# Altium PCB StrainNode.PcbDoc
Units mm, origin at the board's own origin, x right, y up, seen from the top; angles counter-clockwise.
Board outline 65 x 65 mm, 4 copper layers (Top Layer 1, GND, 3V3, Bottom Layer 1), stack 0.408 mm thick; 79 components, 56 nets, 295 pads, 250 vias.
Unrouted connection lines stored in the file: 29.
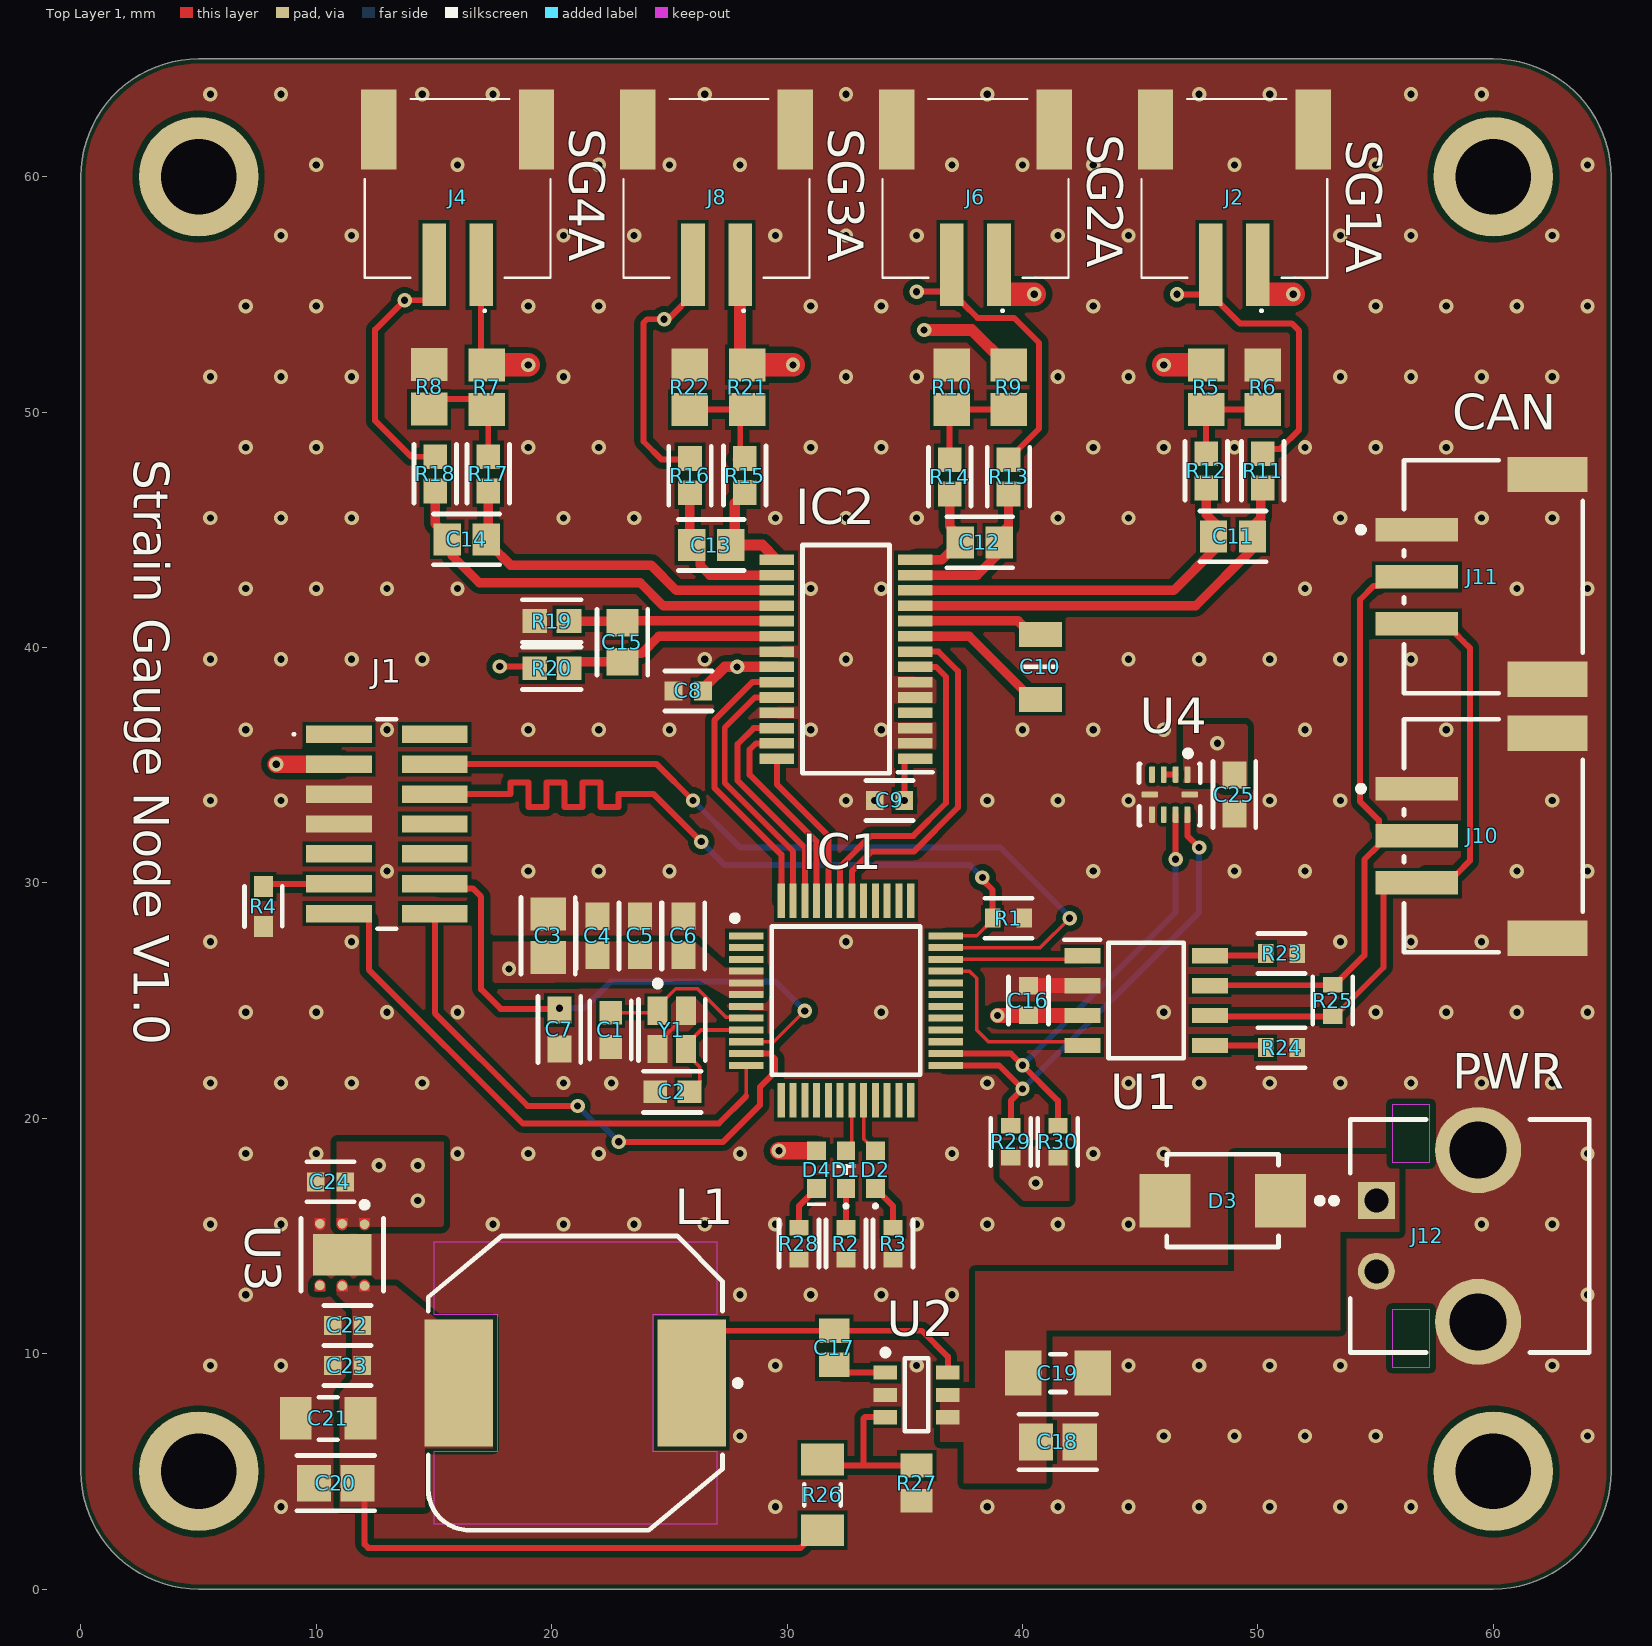
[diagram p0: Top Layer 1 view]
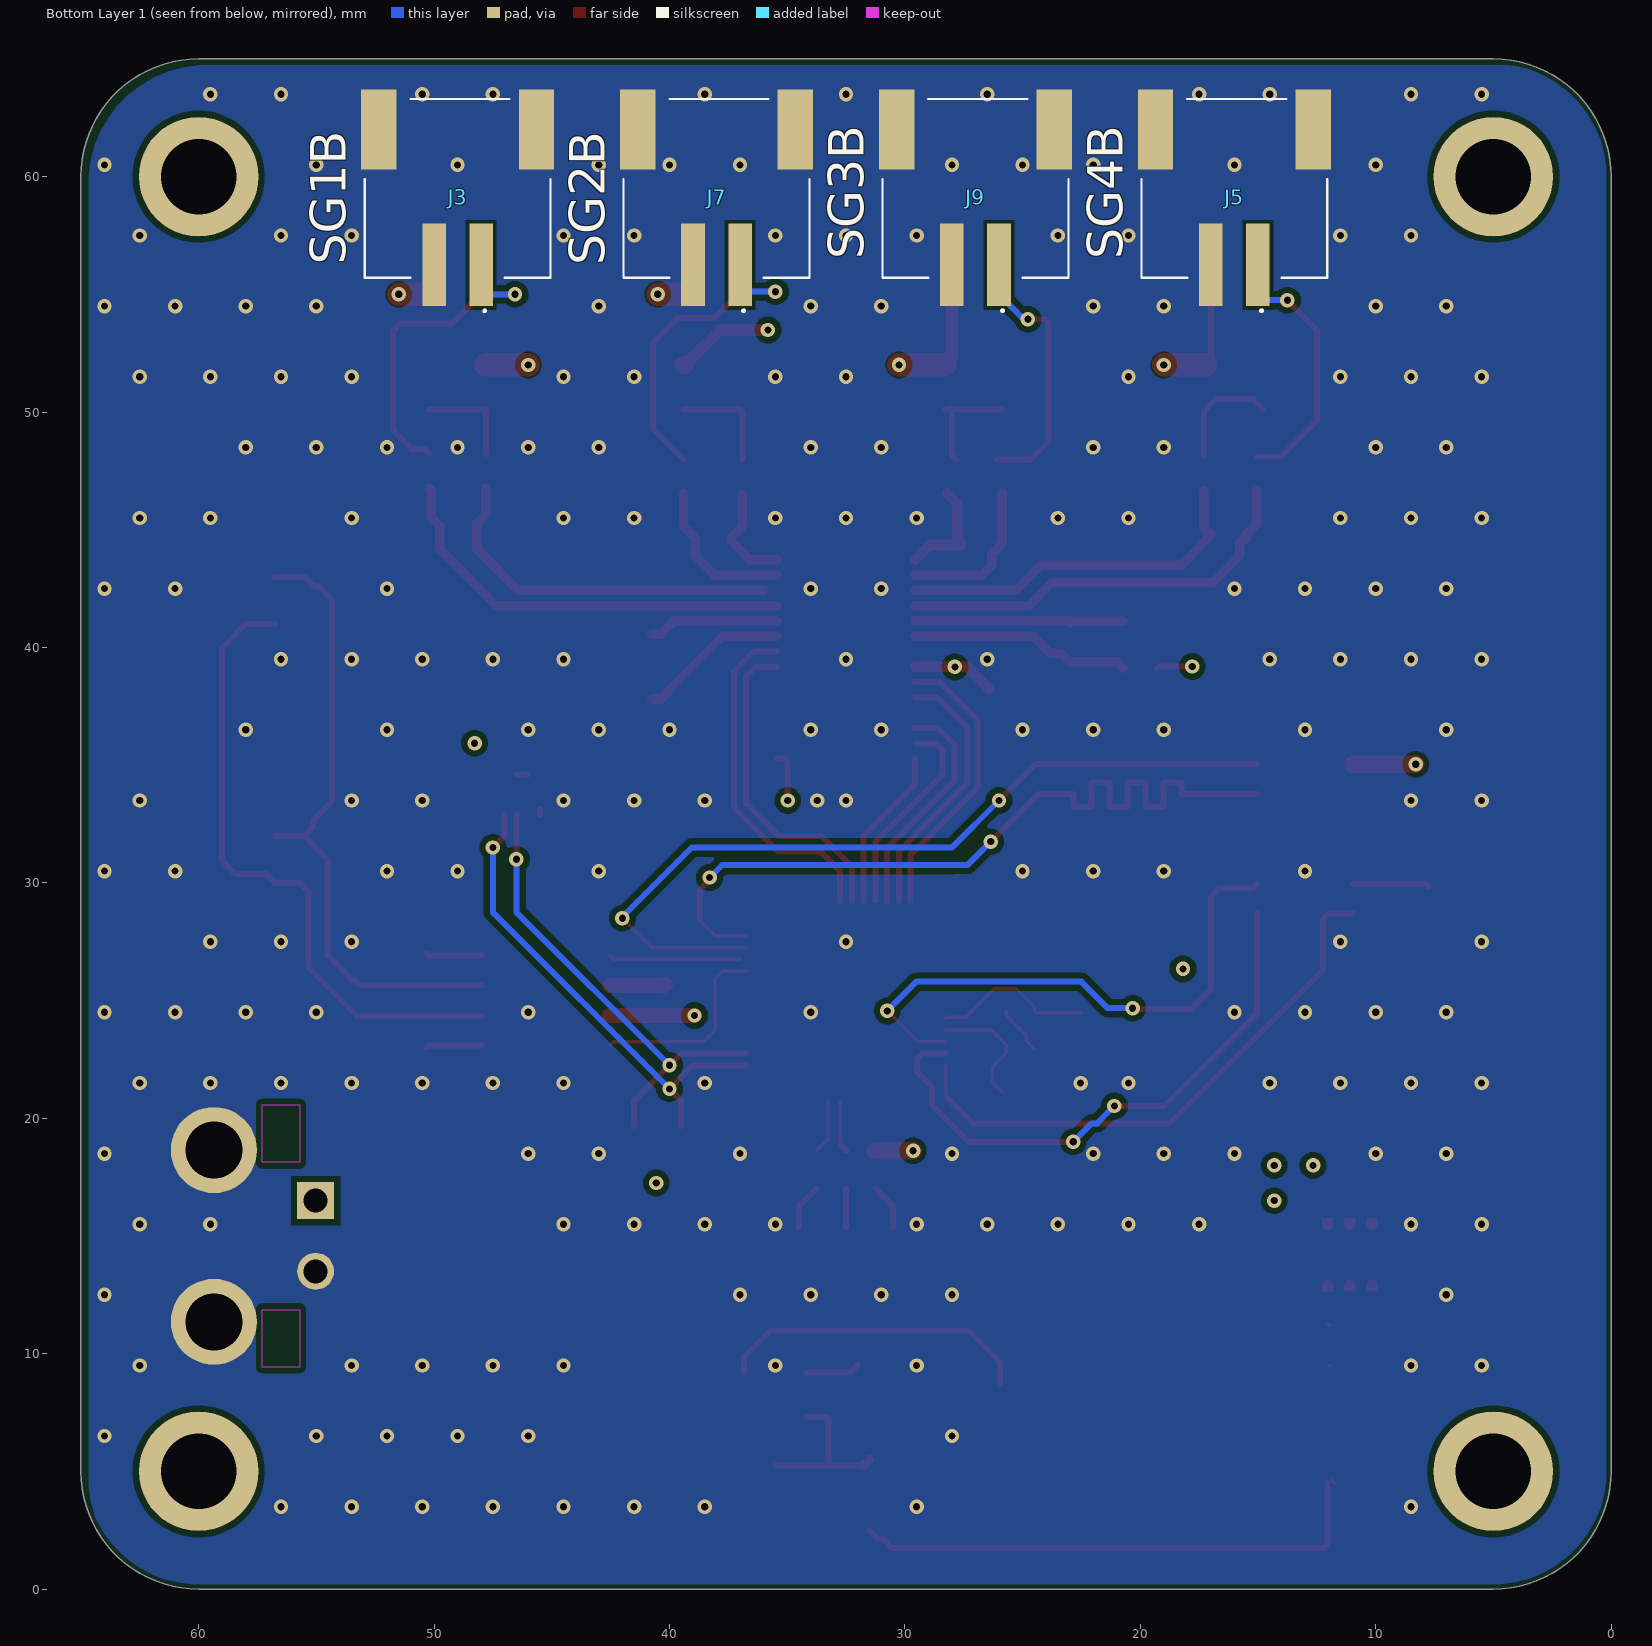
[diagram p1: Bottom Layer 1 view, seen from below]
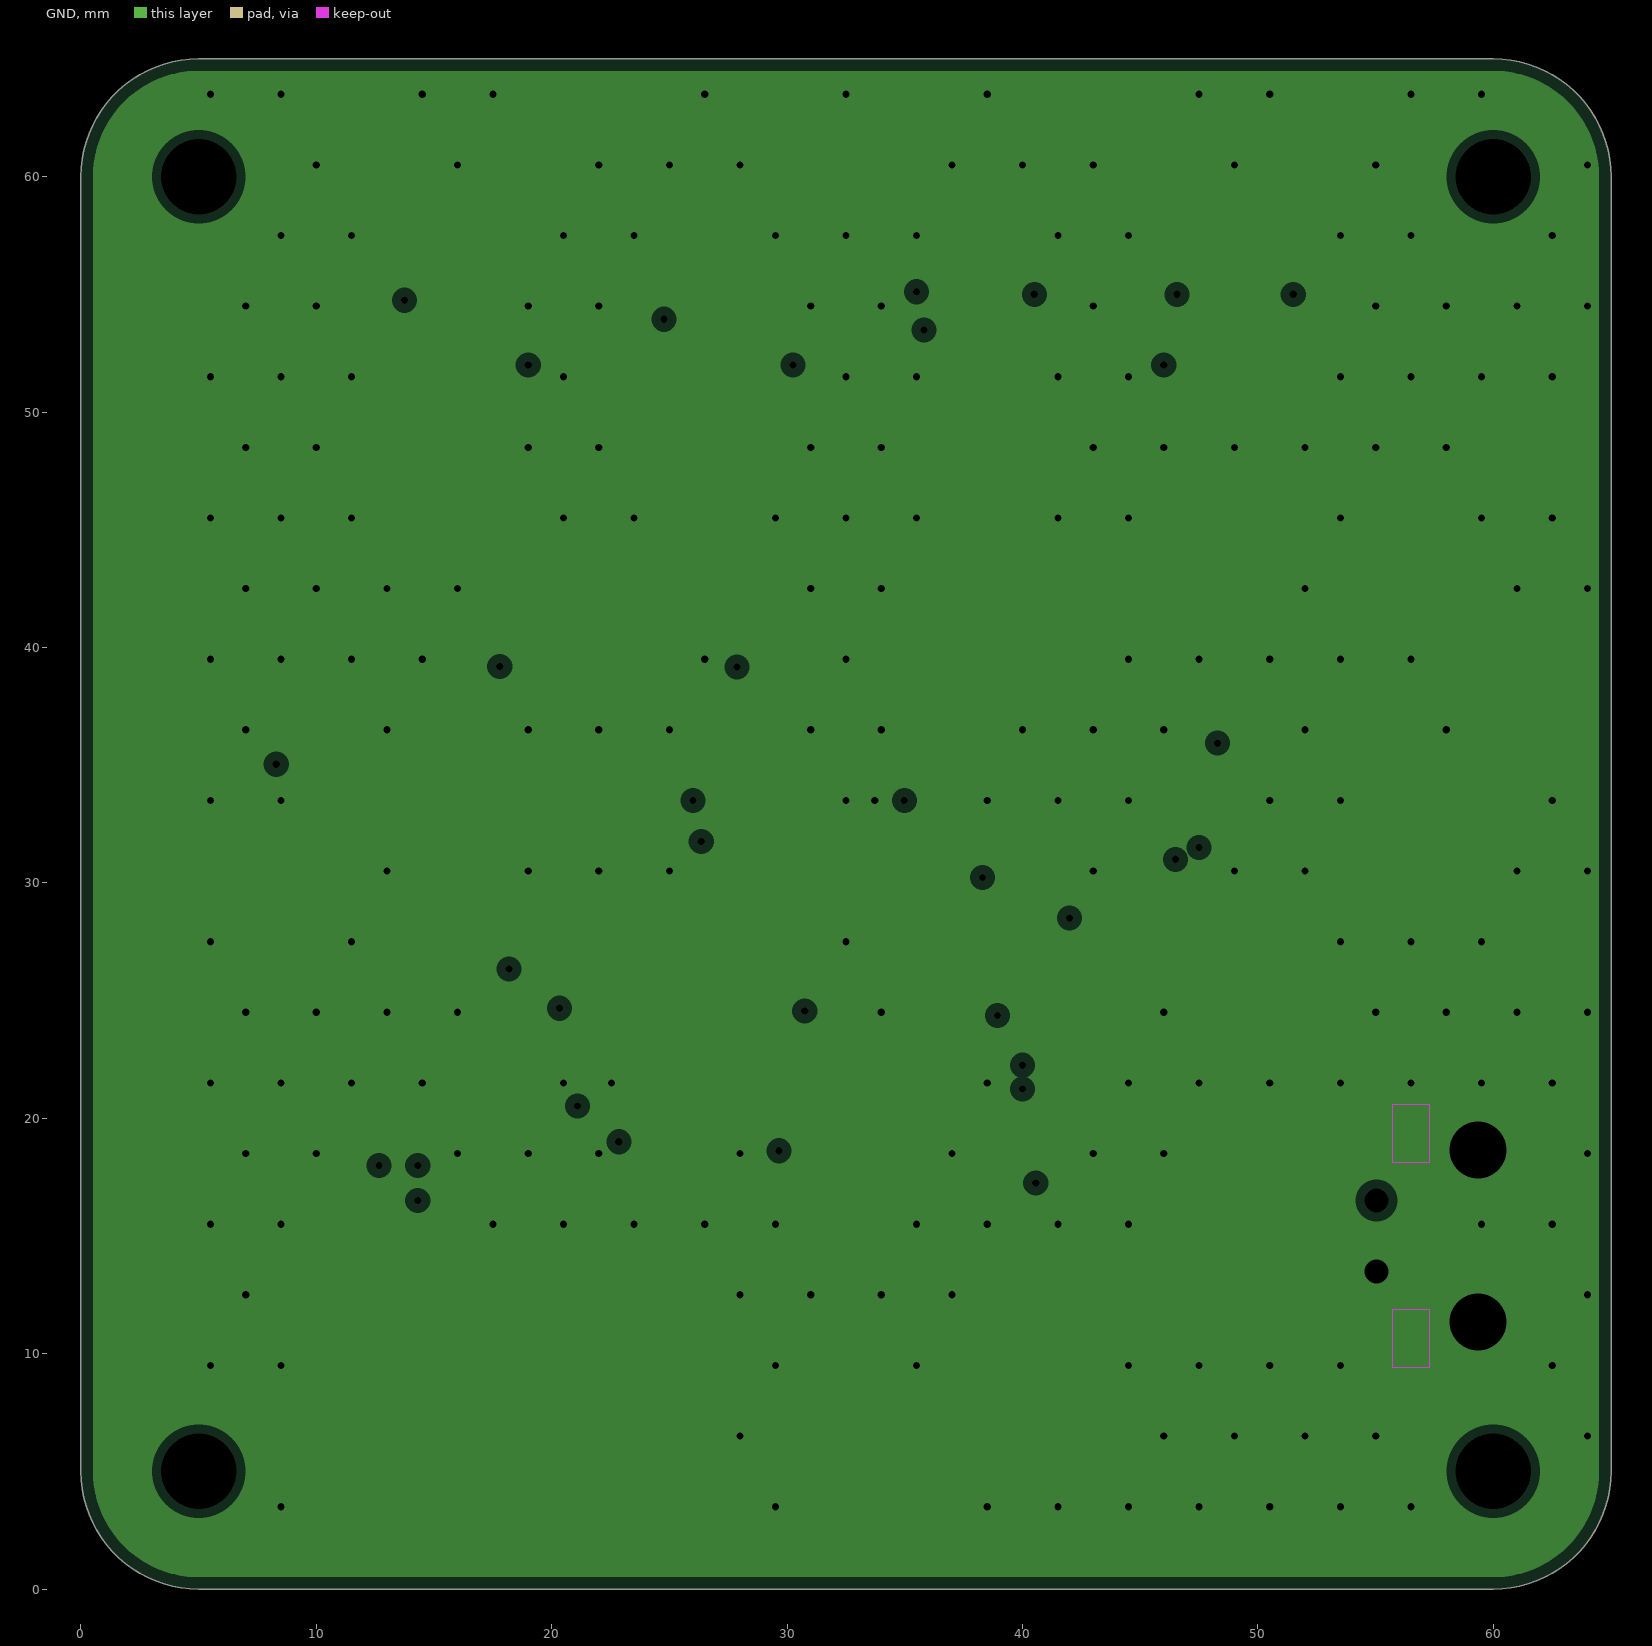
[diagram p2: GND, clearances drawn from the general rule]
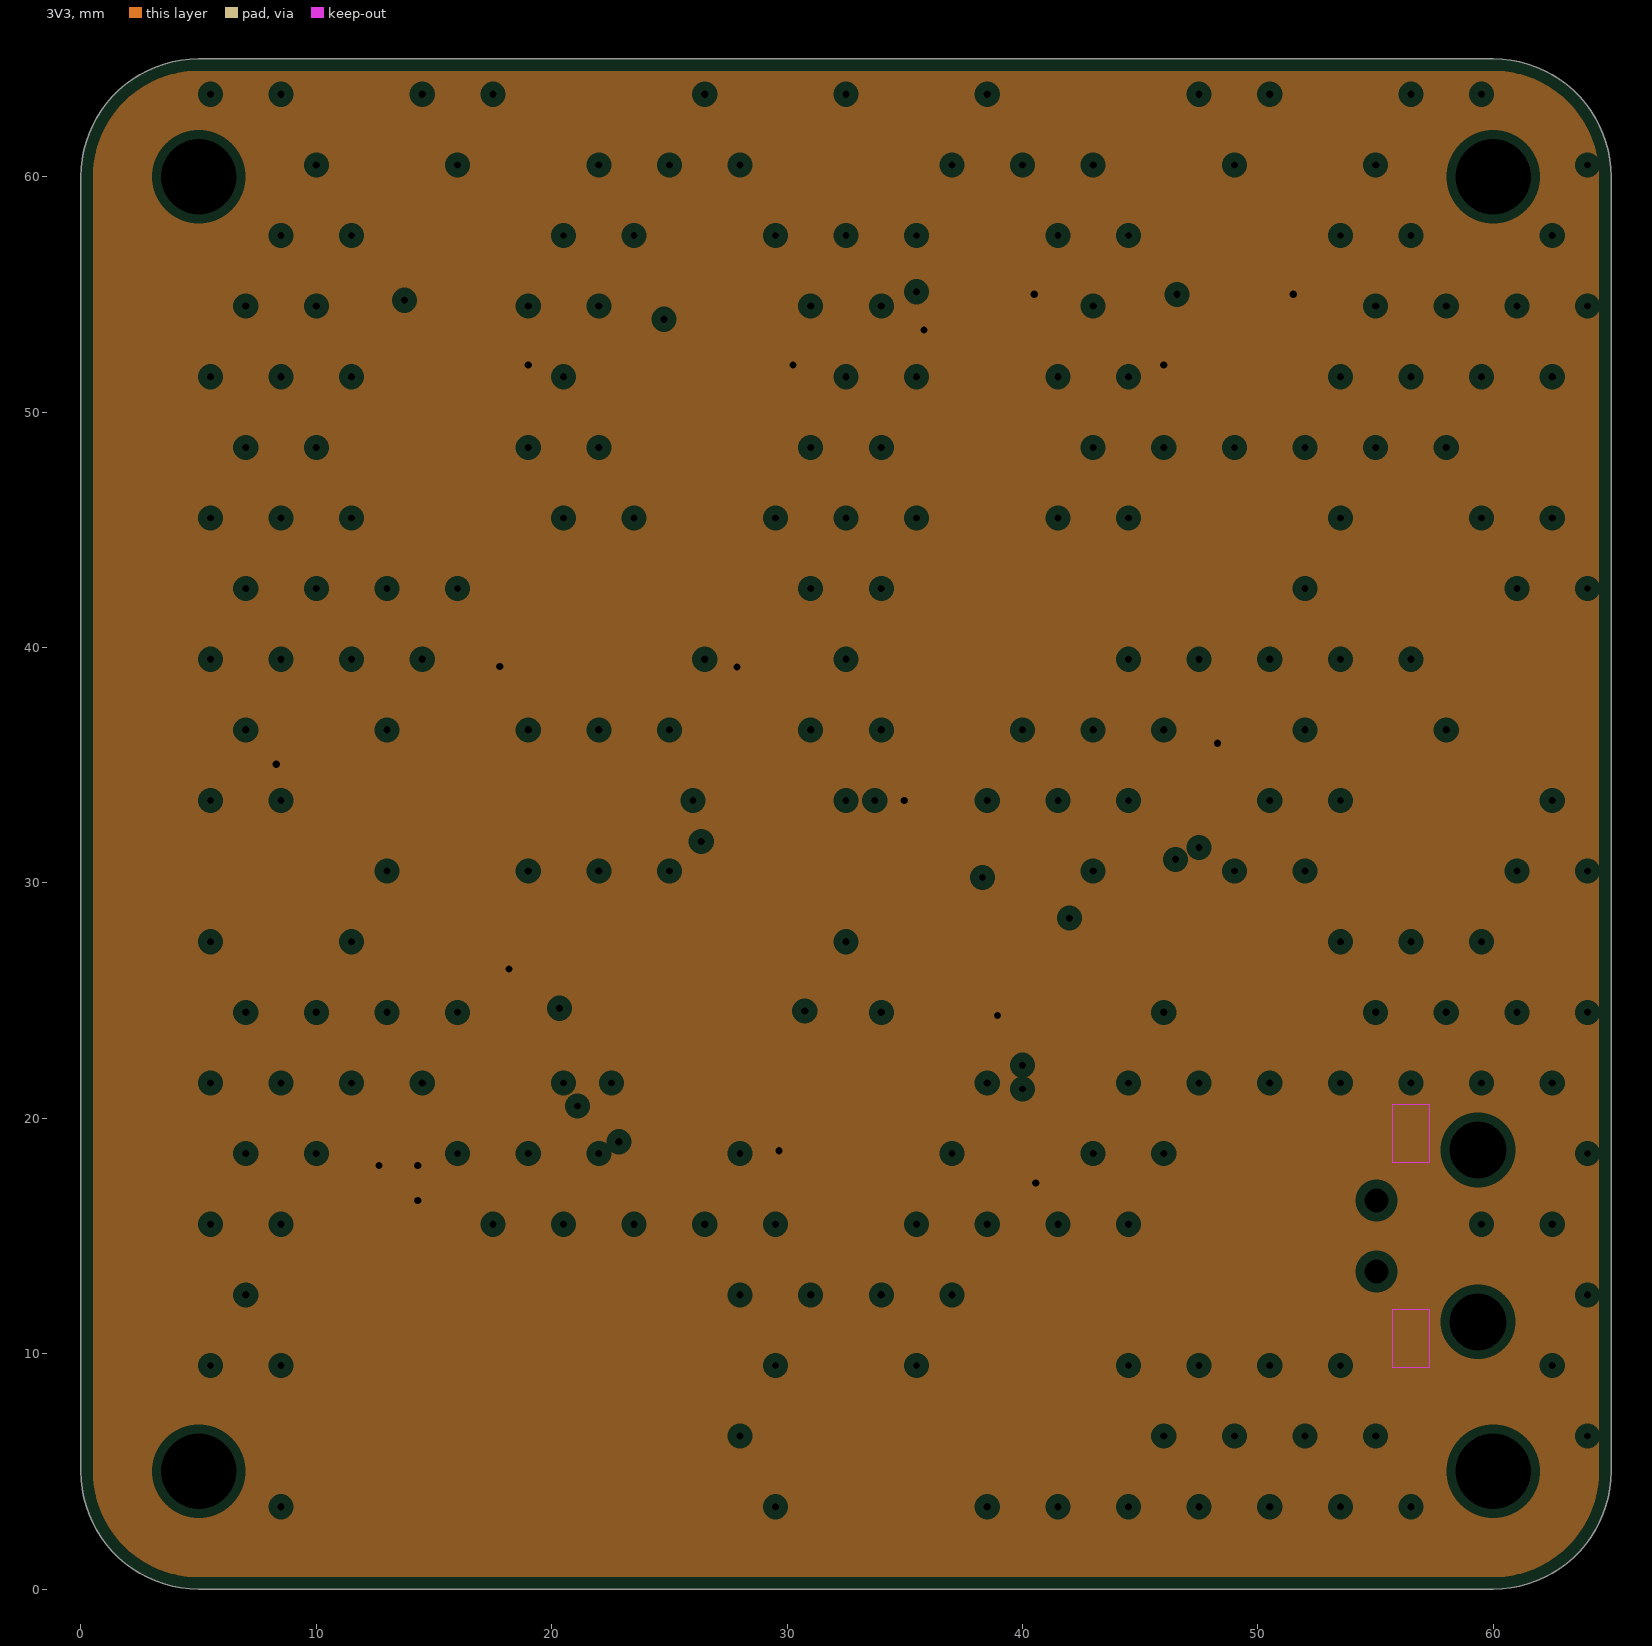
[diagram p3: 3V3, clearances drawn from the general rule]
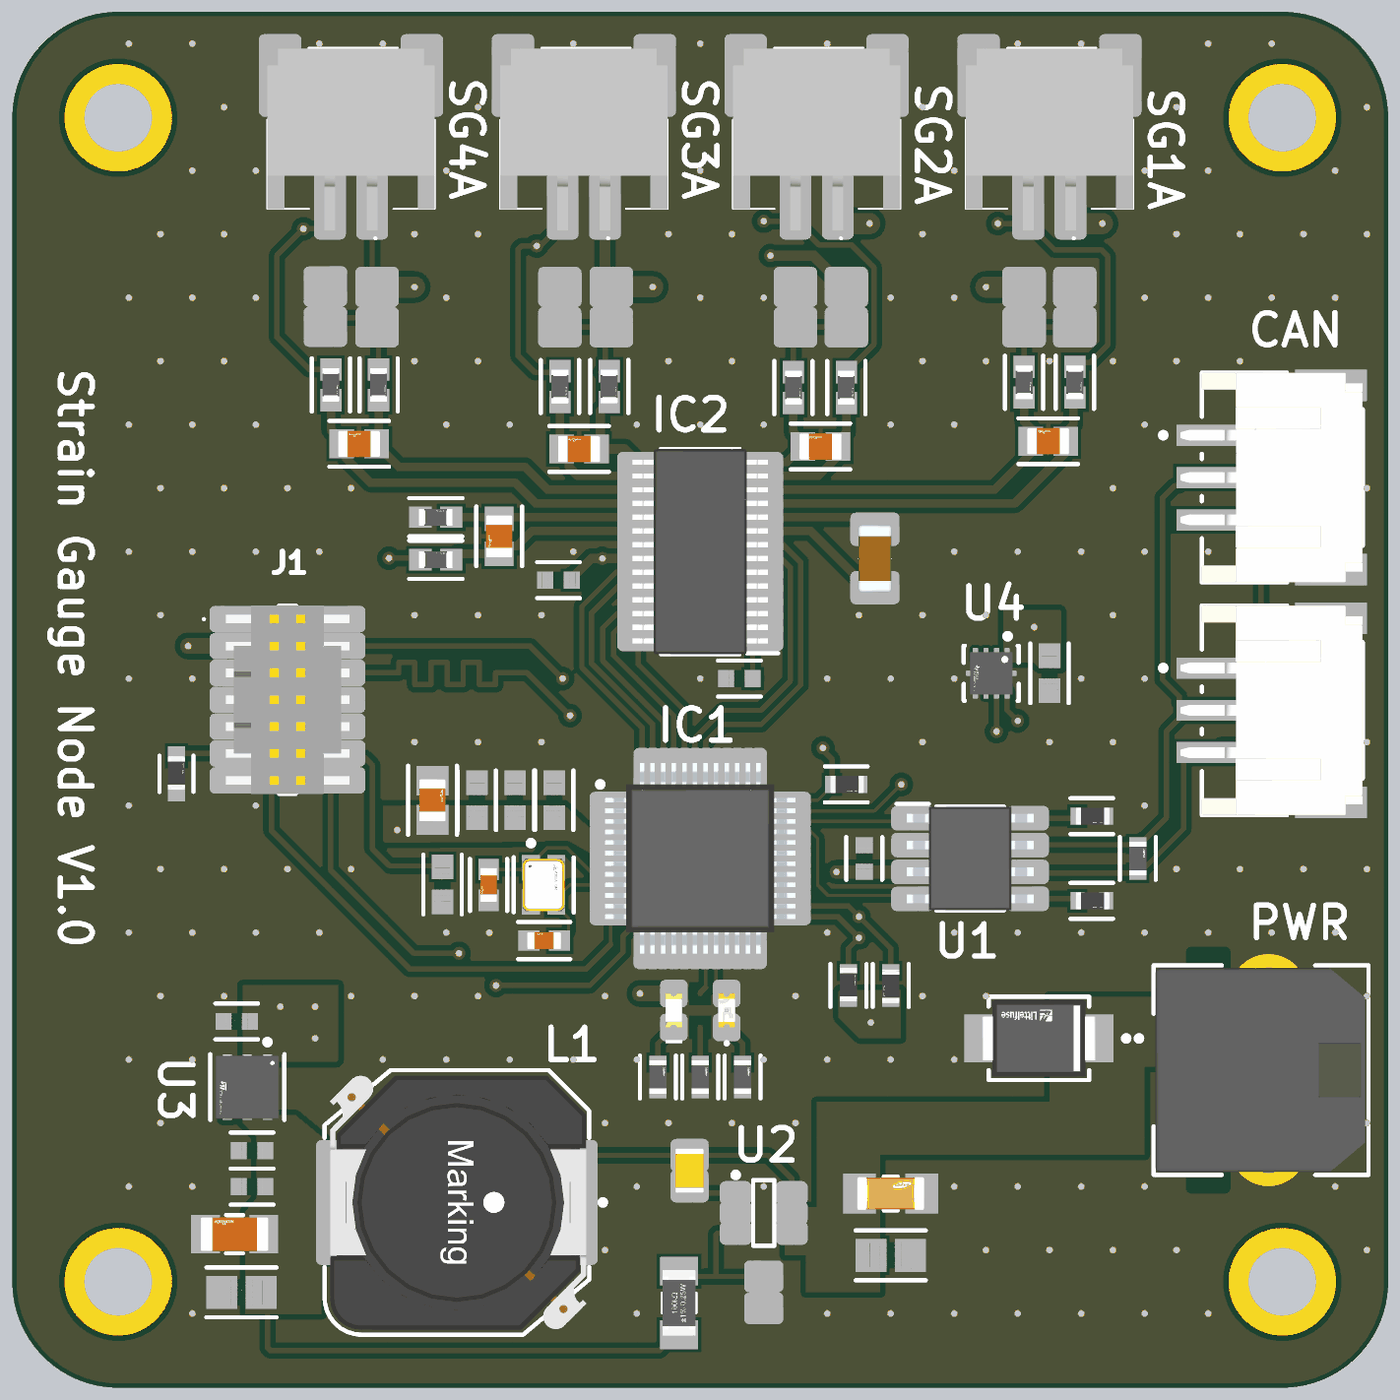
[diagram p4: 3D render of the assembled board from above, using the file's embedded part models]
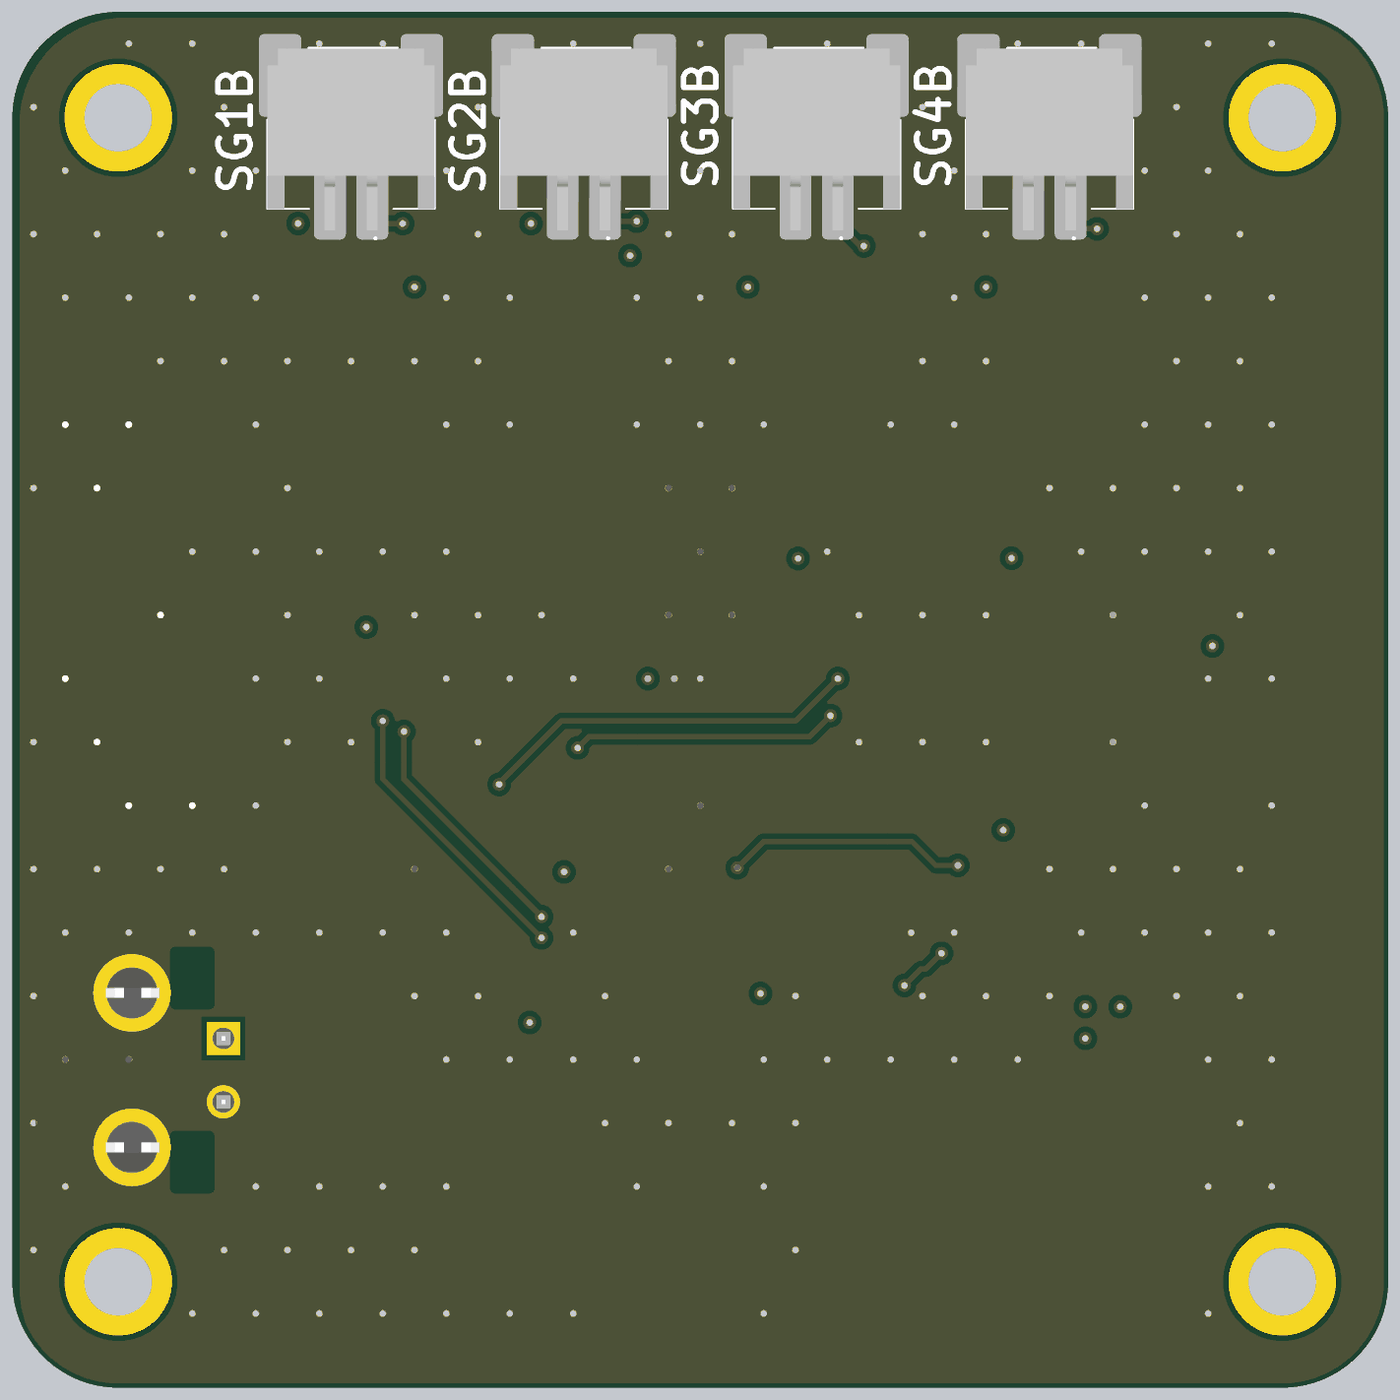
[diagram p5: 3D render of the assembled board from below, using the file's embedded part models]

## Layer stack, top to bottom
Top Solder: solder mask 0.0102, Solder Resist, Dk 3.5
Top Layer 1: signal copper 0.035
Dielectric 2: prepreg 0.0994, PP-006, Dk 4.1
GND: plane copper 0.0152, net GND
Dielectric 1: core 0.1088, FR-4, Dk 4.8
3V3: plane copper 0.0152, net 3V3
Dielectric 3: prepreg 0.0994, PP-006, Dk 4.1
Bottom Layer 1: signal copper 0.035
Bottom Solder: solder mask 0.0102, Solder Resist, Dk 3.5

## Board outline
0,5 ccw(c5,5) 5,0 60,0 ccw(c60,5) 65,5 65,60 ccw(c60,60) 60,65 5,65 ccw(c5,60) 0,60

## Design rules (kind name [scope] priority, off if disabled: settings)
BoardOutlineClearance [All] p1: gap=0.2 ignorepadtopadclearanceinfootprint=FALSE
Clearance "Stitching GND" [IsStitchingVia and InNet('GND') vs (IsVia and (Not IsStitchingVia)) Or IsPad] p1: gap=0.127 ignorepadtopadclearanceinfootprint=FALSE
Clearance [All] p2: gap=0.254 ignorepadtopadclearanceinfootprint=TRUE except(0.1: Arc-Arc Arc-Track Arc-SMDPad Track-Track Track-SMDPad; 0.15: Arc-Text Track-Text SMDPad-SMDPad SMDPad-Fill SMDPad-Poly SMDPad-Region SMDPad-Text THPad-Text Via-Text; 0.2: Arc-Via Track-Via; 0.35: Arc-THPad Track-THPad)
ComponentClearance ComponentClearance_1 [InComponent('L1','L2','L3','C24','C25','C26','C27') vs InComponent('L1','L2','L3','C24','C25','C26','C27')] p1 off: gap=0 collisioncheckmode=3 verticalgap=0 showdistances=FALSE
ComponentClearance [All] p2: gap=0 collisioncheckmode=3 verticalgap=0 showdistances=FALSE
DiffPairsRouting [All] p1: maxlimit=0.254 minlimit=0.254 mostfreqgap=0.254 toplayer_minwidth=0.254 toplayer_maxwidth=0.254 toplayer_prefwidth=0.254 bottomlayer_minwidth=0.254 bottomlayer_maxwidth=0.254 bottomlayer_prefwidth=0.254 maxuncoupledlength=12.7
HoleSize [All] p1: absolutevalues=TRUE maxlimit=7.62 minlimit=0.2 maxpercent=80.000 minpercent=20.000
MinimumAnnularRing [All] p1: minimumring=0.1
MinimumSolderMaskSliver [All] p1: minsoldermaskwidth=0.1
PasteMaskExpansion PasteMaskExpansion_1 [InPadClass('All Pads')] p1: expansion=0
PasteMaskExpansion [All] p2: expansion=0.254
PlaneClearance [All] p1: clearance=0.381
PlaneConnect [All] p1: pad.planeconnectstyle=Relief pad.reliefexpansion=0.508 pad.reliefentries=4 pad.reliefconductorwidth=0.254 pad.reliefairgap=0.254 via.planeconnectstyle=Direct via.reliefexpansion=0.508 via.reliefentries=4 via.reliefconductorwidth=0.254 via.reliefairgap=0.254
PolygonConnect [All] p1: connectstyle=Direct reliefconductorwidth=0.254 reliefentries=4 polygonreliefangle="90 Angle" airgapwidth=0.254
RoutingVias [All] p1: holewidth=0.305 width=0.61 viastyle="Through Hole" minholewidth=0.15 minwidth=0.25 maxholewidth=25.4 maxwidth=25.4
SMDNeckDown [All] p1 off: percent=100.000
SilkToSilkClearance [All] p1 off: silktosilkclearance=0.254
SilkToSolderMaskClearance SilkscreenOverComponentPads [IsPad] p1: minsilkscreentomaskgap=0.15 clearancetoexposedcopper=TRUE
SolderMaskExpansion [InPadClass('All Pads')] p1: expansion=0 istentingtop=FALSE useseparateexpansions=TRUE expansionbottom=0 istentingbottom=FALSE
SolderMaskExpansion SolderMaskExpansion_1 [All] p2: expansion=0.025 istentingtop=TRUE useseparateexpansions=TRUE expansionbottom=0.025 istentingbottom=TRUE
SupplyNets "Schematic Supply Nets_3" [InNet('3V3')] p1: voltage=0.000
SupplyNets "Schematic Supply Nets_2" [InNet('GND')] p2: voltage=0.000
SupplyNets "Schematic Supply Nets_1" [InNet('Vin')] p3: voltage=0.000
SupplyNets "Schematic Supply Nets" [InNet('5V0')] p4: voltage=0.000
UnRoutedNet [All] p1: checkbadconnections=TRUE
Width [All] p1: maxlimit=1.27 minlimit=0.127 preferedwidth=0.254
20 further rules are at their usual default settings.

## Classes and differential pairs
component class "Local PCB temperature sensor": C25 R29 R30 U4
component class "Power supply": C17 C18 C19 C20 C21 C22 C23 C24 D3 D4 J12 L1 R26 R27 R28 U2 U3
component class CAN_Tranceiver: C16 J10 J11 R23 R24 R25 U1
component class Toplevel: C1 C2 C3 C4 C5 C6 C7 D1 D2 IC1 J1 R1 R2 R3 R4 Y1
component class "Strain gauges": C8 C9 C10 C11 C12 C13 C14 C15 IC2 J2 J3 J4 J5 J6 J7 J8 J9 R5 R6 R7 R8 R9 R10 R11 R12 R13 R14 R15 R16 R17 R18 R19 R20 R21 R22 SG1-B

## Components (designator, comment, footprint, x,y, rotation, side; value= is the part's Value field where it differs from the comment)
C1 "4pF" FP-GQM187-0_15-IPC_B 22.5,23.75 r270 top
C2 "4pF" FP-GQM187-0_15-IPC_B 25.127,21.123 r180 top
C3 "4.7uF" FP-GCM21B-0_15-IPC_A 19.85,27.75 r90 top
C4 "100nF" FP-CL10-IPC_A 21.95,27.75 r90 top
C5 "100nF" FP-CL10-IPC_A 23.75,27.75 r90 top
C6 "100nF" FP-CL10-IPC_A 25.6,27.75 r90 top
C7 "100nF" FP-CL10-IPC_A 20.325,23.774 r270 top
C8 "100nF" FP-CL10-IPC_C 25.804,38.15 r180 top
C9 "100nF" FP-CL10-IPC_C 34.35,33.5 r180 top
C10 "100nF" CAPC3216X180N 40.755,39.175 r270 top
C11 "GRM2195C1H103JA01D" FP-GRM219-0_1-IPC_B 48.941,44.716 r180 top
C12 "GRM2195C1H103JA01D" FP-GRM219-0_1-IPC_B 38.181,44.466 r180 top
C13 "GRM2195C1H103JA01D" FP-GRM219-0_1-IPC_B 26.774,44.35 r180 top
C14 "GRM2195C1H103JA01D" FP-GRM219-0_1-IPC_B 16.386,44.591 r180 top
C15 "GRM2195C1H103JA01D" FP-GRM219-0_1-IPC_B 23,40.222 r270 top
C16 "1uF" FP-CL10-IPC_C 40.25,25 r90 top
C17 "Capacitor 100 nF +/-10% 50 V 0805" CAPC2013X95X50LL10T25 32,10.25 r270 top value=100nF
C18 "CL21B474KBFNNNF" FP-CL21-IPC_A 41.5,6.25 r0 top value=470nF
C19 "CL31B106KBHNNNE" FP-CL31B106KBHNNNE-IPC_A 41.5,9.172 r0 top value=10µF
C20 "CL21B474KBFNNNF" FP-CL21-IPC_A 10.824,4.5 r180 top value=470nF
C21 "GRM31CR61A476KE15K" FP-GRM31C-0_2-e0_3_0_8-IPC_B 10.5,7.25 r180 top value=47µF
C22 "100nF" FP-CL10-IPC_C 11.324,11.2 r180 top
C23 "10uF" FP-CL10-IPC_C 11.324,9.494 r180 top
C24 "10uF" FP-CL10-IPC_C 10.6,17.3 r180 top
C25 "100nF" FP-CL10-IPC_A 49,33.75 r270 top
D1 "150060GS55040" WL-SMCD_0603 -1237.5,1287.82 r90 top
D2 "150060YS75020" WL-SMCW_0603_150060xx75020 33.75,17.82 r90 top
D3 "SMBJ33A" FP-SMBJ-MFG 48.5,16.5 r180 top
D4 "150060RS75000" WL-SMCW_0603_150060xx75000 31.25,17.82 r90 top
IC1 "STM32G0B1CBT6" QFP50P900X900X160-48N 32.5,25 r0 top locked
IC2 "ADS1234IPWR" SOP65P640X120-28N 32.5,39.5 r180 top locked
J1 "FTSH-107-01-L-DV-K-TR" FTSH10701LDVKTR 13,32.5 r270 top
J2 "S2B-PH-SM4-TB_LF__SN_" S2BPHSM4TBLFSN 49,59.5 r0 top locked
J3 "S2B-PH-SM4-TB_LF__SN_" S2BPHSM4TBLFSN 49,59.5 r180 bottom locked
J4 "S2B-PH-SM4-TB_LF__SN_" S2BPHSM4TBLFSN 16,59.5 r0 top locked
J5 "S2B-PH-SM4-TB_LF__SN_" S2BPHSM4TBLFSN 16,59.5 r180 bottom
J6 "S2B-PH-SM4-TB_LF__SN_" S2BPHSM4TBLFSN 38,59.5 r0 top locked
J7 "S2B-PH-SM4-TB_LF__SN_" S2BPHSM4TBLFSN 38,59.5 r180 bottom
J8 "S2B-PH-SM4-TB_LF__SN_" S2BPHSM4TBLFSN 27,59.5 r0 top locked
J9 "S2B-PH-SM4-TB_LF__SN_" S2BPHSM4TBLFSN 27,59.5 r180 bottom
J10 "S3B-PH-SM4-TB(LF)(SN)" FP-S3B-PH-SM4-TB_LF_SN-MFG 60,32 r270 top locked
J11 "S3B-PH-SM4-TB(LF)(SN)" FP-S3B-PH-SM4-TB_LF_SN-MFG 60,43 r270 top locked
J12 "43650-0205" FP-43650-0205-MFG 59,15 r90 top
L1 "7447706330" WE-PD_1260P 21,8.75 r270 top value=33uH
R1 "10k" FP-RT0603-IPC_C 39.4,28.5 r0 top value=10KΩ
R2 "220 0603" FP-AF0603-IPC_C 32.5,14.677 r90 top
R3 "220 0603" FP-AF0603-IPC_C 34.5,14.677 r90 top
R4 "100" FP-RT0603-MFG 7.75,29 r90 top value=100Ω
R5 "120" RESC2013X60X40ML20T25 47.8,51.05 r90 top
R6 "120" RESC2013X60X40ML20T25 50.2,51.05 r270 top
R7 "120" RESC2013X60X40ML20T25 17.234,51.05 r90 top
R8 "120" RESC2013X60X40ML20T25 14.789,51.076 r270 top
R9 "120" RESC2013X60X40ML20T25 39.403,51.05 r90 top
R10 "120" RESC2013X60X40ML20T25 37,51.05 r270 top
R11 "100" FP-ERA3A-IPC_B 50.2,47.5 r270 top
R12 "100" FP-ERA3A-IPC_B 47.8,47.5 r270 top
R13 "100" FP-ERA3A-IPC_B 39.403,47.25 r270 top
R14 "100" FP-ERA3A-IPC_B 36.903,47.25 r270 top
R15 "100" FP-ERA3A-IPC_B 28.202,47.301 r270 top
R16 "100" FP-ERA3A-IPC_B 25.871,47.297 r270 top
R17 "100" FP-ERA3A-IPC_B 17.303,47.376 r270 top
R18 "100" FP-ERA3A-IPC_B 15.05,47.376 r270 top
R19 "100" FP-ERA3A-IPC_B 20.005,41.121 r0 top
R20 "100" FP-ERA3A-IPC_B 20.005,39.115 r0 top
R21 "120" RESC2013X60X40ML20T25 28.299,51.054 r90 top
R22 "120" RESC2013X60X40ML20T25 25.866,51.05 r270 top
R23 "10k" FP-RT0603-IPC_C 51,27 r0 top value=10KΩ
R24 "10k" FP-RT0603-IPC_C 51,23 r0 top value=10KΩ
R25 "120" FP-AF0603-IPC_C 53.175,25 r90 top
R26 "CRGCQ1206F100K" FP-CRGCQ1206-IPC_A 31.5,4 r90 top value=100k
R27 "ERA-6AEB1872V" RESC2013X60X40LL20T25 35.5,4.5 r270 top value=18.7k
R28 "220 0603" FP-AF0603-IPC_C 30.5,14.677 r90 top
R29 "10k" FP-RT0603-IPC_C 39.5,19 r90 top value=10KΩ
R30 "10k" FP-RT0603-IPC_C 41.5,19 r270 top value=10KΩ
U1 "TCAN3414DR" SOIC127P600X175-8N 45.25,25 r0 top locked
U2 "LMR51610XDBVR" SOT95P280X145-6N 35.5,8.25 r0 top
U3 "LD39200PU33R" FP-DFN6-7946637-MFG 11.1,14.2 r270 top
U4 "TMP461AIRUNR-S" FP-RUN0010A-MFG 46.25,33.75 r270 top
Y1 "ABM10W-50.0000MHZ-4-B1U-T3" FP-ABM10W-MFG 25.099,23.75 r270 top

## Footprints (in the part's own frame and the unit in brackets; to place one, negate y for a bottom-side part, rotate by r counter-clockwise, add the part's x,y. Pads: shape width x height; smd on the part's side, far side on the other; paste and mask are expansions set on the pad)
CAPC2013X95X50LL10T25 [mm] "Chip Capacitor, 2-Leads, Body 2.10x1.35mm, IPC High Density"
  rect 1.05x1.3 smd: 1(-0.725,0) 2(0.725,0)
  body extent -1.05,-0.67 1.05,0.67, height 0.95
CAPC3216X180N [mm]
  rect 1.07x1.82 smd: 1(-1.38,0) 2(1.38,0)
  silkscreen extent 0,-0.7 0,0.7, body extent -1.6,-0.8 1.6,0.8, height 1.8
FP-43650-0205-MFG [mm]
  rect 1.57x1.57 hole 1.02 paste-2539.97 mask+0: 1(1.5,3.97)
  round 1.57 hole 1.02 paste-2539.97 mask+0: 2(-1.5,3.97)
  round 3.66 hole 2.41 paste-2539.97 mask+0: 3(-3.65,-0.35) 4(3.65,-0.35)
  Keep-Out Layer region: -5.575,1.7 -3.125,1.7 -3.125,3.3 -5.575,3.3
  Keep-Out Layer region: 3.125,1.7 5.575,1.7 5.575,3.3 3.125,3.3
  silkscreen extent -4.95,-5.08 4.95,5.89, body extent -5.58,-5.18 5.58,5.18, height 0.25
FP-ABM10W-MFG [mm]
  rect 1.2x0.85 smd paste+0 mask+0: 1(-0.812,-0.6) 2(0.812,-0.6) 3(0.812,0.6) 4(-0.812,0.6)
  silkscreen extent -2.1,-1.41 1.3,1.42, body extent -1.51,-1.15 1.51,1.15, height 0.25
FP-AF0603-IPC_C [mm]
  rect 0.659x0.812 smd paste+0 mask+0: 1(-0.677,0) 2(0.677,0)
  silkscreen extent -1.01,-0.85 1.01,0.85, body extent -1.11,-0.55 1.11,0.55, height 0.25
FP-CL10-IPC_A [mm]
  rect 1.158x1.012 smd paste+0 mask+0: 1(-0.827,0) 2(0.827,0)
  silkscreen extent -1.41,-0.91 1.41,0.91, body extent -1.91,-1.01 1.91,1.01, height 0.25
FP-CL10-IPC_C [mm]
  rect 0.758x0.812 smd paste+0 mask+0: 1(-0.627,0) 2(0.627,0)
  silkscreen extent -1.01,-0.85 1.01,0.85, body extent -1.11,-0.55 1.11,0.55, height 0.25
FP-CL21-IPC_A [mm]
  rect 1.455x1.556 smd paste+0 mask+0: 1(-0.926,0) 2(0.926,0)
  silkscreen extent -1.65,-1.18 1.65,1.18, body extent -2.15,-1.28 2.15,1.28, height 0.25
FP-CL31B106KBHNNNE-IPC_A [mm]
  rect 1.554x1.906 smd paste+0 mask+0: 1(-1.476,0) 2(1.476,0)
  silkscreen extent -0.32,-0.8 0.32,0.8, body extent -2.75,-1.45 2.75,1.45, height 0.25
FP-CRGCQ1206-IPC_A [mm]
  rect 1.356x1.81 smd paste+0 mask+0: 1(-1.501,0) 2(1.501,0)
  silkscreen extent -0.45,-0.77 0.45,0.78, body extent -2.68,-1.4 2.68,1.4, height 0.25
FP-DFN6-7946637-MFG [mm]
  round 0.405 smd paste+0 mask+0: 1(-1.3,0.95) 2(-1.321,0) 3(-1.321,-0.95) 4(1.3,-0.95) 5(1.321,0) 6(1.321,0.95)
  rect 1.75x2.5 smd paste+0 mask+0: 7(0,0)
  Top Layer 1 region: -1.55,0.225 -1.275,0.225 -1.189,0.208 -1.116,0.159 -1.067,0.086 -1.05,0 -1.05,0 -1.067,-0.086 -1.116,-0.159 -1.189,-0.208 -1.275,-0.225 -1.275,-0.225 -1.55,-0.225
  Top Layer 1 region: -1.55,1.175 -1.275,1.175 -1.189,1.158 -1.116,1.109 -1.067,1.036 -1.05,0.95 -1.05,0.95 -1.067,0.864 -1.116,0.791 -1.189,0.742 -1.275,0.725 -1.275,0.725 -1.55,0.725
  Top Layer 1 region: -1.55,-0.725 -1.275,-0.725 -1.189,-0.742 -1.116,-0.791 -1.067,-0.864 -1.05,-0.95 -1.05,-0.95 -1.067,-1.036 -1.116,-1.109 -1.189,-1.158 -1.275,-1.175 -1.275,-1.175 -1.55,-1.175
  Top Layer 1 region: 1.55,0.725 1.275,0.725 1.189,0.742 1.116,0.791 1.067,0.864 1.05,0.95 1.05,0.95 1.067,1.036 1.116,1.109 1.189,1.158 1.275,1.175 1.275,1.175 1.55,1.175
  Top Layer 1 region: 1.55,-0.225 1.275,-0.225 1.189,-0.208 1.116,-0.159 1.067,-0.086 1.05,0 1.05,0 1.067,0.086 1.116,0.159 1.189,0.208 1.275,0.225 1.275,0.225 1.55,0.225
  Top Layer 1 region: 1.55,-1.175 1.275,-1.175 1.189,-1.158 1.116,-1.109 1.067,-1.036 1.05,-0.95 1.05,-0.95 1.067,-0.864 1.116,-0.791 1.189,-0.742 1.275,-0.725 1.275,-0.725 1.55,-0.725
  silkscreen extent -2.25,-1.75 1.55,1.75, body extent -1.65,-1.65 1.65,1.65, height 0.25
FP-ERA3A-IPC_B [mm]
  rect 1.055x1.006 smd paste+0 mask+0: 1(-0.726,0) 2(0.726,0)
  silkscreen extent -1.25,-0.9 1.25,0.9, body extent -1.5,-0.75 1.5,0.75, height 0.25
FP-GCM21B-0_15-IPC_A [mm]
  rect 1.406x1.508 smd paste+0 mask+0: 1(-0.926,0) 2(0.926,0)
  silkscreen extent -1.63,-1.15 1.63,1.15, body extent -2.13,-1.25 2.13,1.25, height 0.25
FP-GQM187-0_15-IPC_B [mm]
  rect 1.007x0.958 smd paste+0 mask+0: 1(-0.726,0) 2(0.726,0)
  silkscreen extent -1.23,-0.88 1.23,0.88, body extent -1.48,-0.73 1.48,0.73, height 0.25
FP-GRM31C-0_2-e0_3_0_8-IPC_B [mm]
  rect 1.355x1.806 smd paste+0 mask+0: 1(-1.376,0) 2(1.376,0)
  silkscreen extent -0.4,-0.9 0.4,0.9, body extent -2.3,-1.15 2.3,1.15, height 0.25
FP-GRM219-0_1-IPC_B [mm]
  rect 1.158x1.362 smd paste+0 mask+0: 1(-0.827,0) 2(0.827,0)
  silkscreen extent -1.41,-1.08 1.41,1.08, body extent -1.66,-0.93 1.66,0.93, height 0.25
FP-RT0603-IPC_C [mm]
  rect 0.659x0.812 smd paste+0 mask+0: 1(-0.677,0) 2(0.677,0)
  silkscreen extent -1.01,-0.85 1.01,0.85, body extent -1.11,-0.55 1.11,0.55, height 0.25
FP-RT0603-MFG [mm]
  rect 0.9x0.8 smd paste+0 mask+0: 1(-0.85,0) 2(0.85,0)
  silkscreen extent -0.85,-0.81 0.86,0.8, body extent -1.4,-0.55 1.4,0.55, height 0.25
FP-RUN0010A-MFG [mm]
  rrect40% 0.7x0.25 smd paste+0 mask+0: 1(-0.85,0.75) 2(-0.85,0.25) 3(-0.85,-0.25) 4(-0.85,-0.75) 6(0.85,-0.75) 7(0.85,-0.25) 8(0.85,0.25) 9(0.85,0.75)
  rrect40% 0.25x0.7 smd paste+0 mask+0: 5(0,-0.85) 10(0,0.85)
  silkscreen extent -1.87,-1.3 1.3,1.3, body extent -1.3,-1.3 1.3,1.3, height 0.25
FP-S3B-PH-SM4-TB_LF_SN-MFG [mm]
  rect 1x3.5 smd paste+0 mask+0: 1(-2,-3.25) 2(0,-3.25) 3(2,-3.25)
  rect 1.5x3.4 smd paste+0 mask+0: 4(-4.35,2.3) 5(4.35,2.3)
  silkscreen extent -4.95,-5.75 4.95,3.8, body extent -5.2,-5.1 5.2,4.1, height 0.25
FP-SMBJ-MFG [mm]
  rect 2.16x2.26 smd paste+0 mask+0: 1(-2.45,0) 2(2.45,0)
  silkscreen extent -4.25,-1.97 2.38,1.97, body extent -3.63,-2.07 3.63,2.07, height 0.25
FTSH10701LDVKTR [mm]
  rect 0.74x2.79 smd: 1(-3.81,-2.035) 2(-3.81,2.035) 3(-2.54,-2.035) 4(-2.54,2.035) 5(-1.27,-2.035) 6(-1.27,2.035) 7(0,-2.035) 8(0,2.035) 9(1.27,-2.035) 10(1.27,2.035) 11(2.54,-2.035) 12(2.54,2.035) 13(3.81,-2.035) 14(3.81,2.035)
  silkscreen extent -4.44,-4 4.45,0.4, body extent -4.45,-2.92 4.45,2.92, height 6.12
QFP50P900X900X160-48N [mm]
  rect 1.475x0.3 smd: 1(-4.238,2.75) 2(-4.238,2.25) 3(-4.238,1.75) 4(-4.238,1.25) 5(-4.238,0.75) 6(-4.238,0.25) 7(-4.238,-0.25) 8(-4.238,-0.75) 9(-4.238,-1.25) 10(-4.238,-1.75) 11(-4.238,-2.25) 12(-4.238,-2.75) 25(4.238,-2.75) 26(4.238,-2.25) 27(4.238,-1.75) 28(4.238,-1.25) 29(4.238,-0.75) 30(4.238,-0.25) 31(4.238,0.25) 32(4.238,0.75) 33(4.238,1.25) 34(4.238,1.75) 35(4.238,2.25) 36(4.238,2.75)
  rect 0.3x1.475 smd: 13(-2.75,-4.238) 14(-2.25,-4.238) 15(-1.75,-4.238) 16(-1.25,-4.238) 17(-0.75,-4.238) 18(-0.25,-4.238) 19(0.25,-4.238) 20(0.75,-4.238) 21(1.25,-4.238) 22(1.75,-4.238) 23(2.25,-4.238) 24(2.75,-4.238) 37(2.75,4.238) 38(2.25,4.238) 39(1.75,4.238) 40(1.25,4.238) 41(0.75,4.238) 42(0.25,4.238) 43(-0.25,4.238) 44(-0.75,4.238) 45(-1.25,4.238) 46(-1.75,4.238) 47(-2.25,4.238) 48(-2.75,4.238)
  silkscreen extent -4.85,-3.15 3.15,3.62, body extent -4.5,-4.5 4.5,4.5, height 1.6
RESC2013X60X40LL20T25 [mm] "Chip Resistor, 2-Leads, Body 2.00x1.25mm, IPC High Density"
  rect 1x1.35 smd: 1(-0.75,0) 2(0.75,0)
  body extent -1.1,-0.72 1.1,0.72, height 0.6
RESC2013X60X40ML20T25 [mm] "Chip Resistor, 2-Leads, Body 2.00x1.25mm, IPC Low Density"
  rect 1.4x1.55 smd: 1(-0.95,0) 2(0.95,0)
  body extent -1.1,-0.72 1.1,0.72, height 0.6
S2BPHSM4TBLFSN [mm]
  rect 1x3.5 smd: 1(1,-3.25) 2(-1,-3.25)
  rect 1.5x3.4 smd: MP1(3.35,2.5) MP2(-3.35,2.5)
  silkscreen extent -3.95,-5.25 3.95,3.8, body extent -3.95,-4.83 3.95,3.77, height 5.6
SOIC127P600X175-8N [mm]
  rect 1.525x0.65 smd: 1(-2.712,1.905) 2(-2.712,0.635) 3(-2.712,-0.635) 4(-2.712,-1.905) 5(2.712,-1.905) 6(2.712,-0.635) 7(2.712,0.635) 8(2.712,1.905)
  silkscreen extent -3.47,-2.45 1.6,2.58, body extent -3,-2.45 3,2.45, height 1.75
SOP65P640X120-28N [mm]
  rect 1.475x0.45 smd: 1(-2.938,4.225) 2(-2.938,3.575) 3(-2.938,2.925) 4(-2.938,2.275) 5(-2.938,1.625) 6(-2.938,0.975) 7(-2.938,0.325) 8(-2.938,-0.325) 9(-2.938,-0.975) 10(-2.938,-1.625) 11(-2.938,-2.275) 12(-2.938,-2.925) 13(-2.938,-3.575) 14(-2.938,-4.225) 15(2.938,-4.225) 16(2.938,-3.575) 17(2.938,-2.925) 18(2.938,-2.275) 19(2.938,-1.625) 20(2.938,-0.975) 21(2.938,-0.325) 22(2.938,0.325) 23(2.938,0.975) 24(2.938,1.625) 25(2.938,2.275) 26(2.938,2.925) 27(2.938,3.575) 28(2.938,4.225)
  silkscreen extent -3.67,-4.85 1.85,4.85, body extent -3.2,-4.85 3.2,4.85, height 1.13
SOT95P280X145-6N [mm] "SOT23, 6-Leads, Body 2,90x2,80mm, Pitch 0,95mm, IPC Medium Density"
  rect 1x0.6 smd: 1(-1.325,0.95) 2(-1.325,0) 3(-1.325,-0.95) 4(1.325,-0.95) 5(1.325,0) 6(1.325,0.95)
  silkscreen extent -1.45,-1.55 0.5,1.92, body extent -0.88,-1.52 0.87,1.53, height 1.45
WE-PD_1260P [mm] "SMT Shielded Power Inductor, 2-leads, body 12x12mm"
  rect 5.4x2.9 smd: 1(0,4.95) 2(0,-4.95)
  Top Layer 1 keep-out region: -6,6 -2.9,6 -2.9,3.3 2.9,3.3 2.9,6 6,6 6,-6 2.9,-6 2.9,-3.3 -2.9,-3.3 -2.9,-6 -6,-6
  silkscreen extent -6.25,-6.25 6.25,7.03, body extent -5.99,-6.01 6.01,6.14, height 5.75
WL-SMCD_0603 [mm] "SMD Mono-color Chip LED, body 1.6x0.8mm"
  rect 0.8x0.75 smd: 1(-1270.8,-1270) 2(-1269.2,-1270)
  silkscreen extent -1271.62,-1270.4 -1269.78,-1269.6, body extent -1270.8,-1270.4 -1269.2,-1269.6, height 0.42
WL-SMCW_0603_150060xx75000 [mm] "SMD Mono-color Chip LED, body 1.60 x 0.80 mm"
  rect 0.8x0.8 smd: 1(-0.8,0) 2(0.8,0)
  silkscreen extent -1.55,-0.4 -1.4,0.4, body extent -0.8,-0.4 0.8,0.4, height 0.7
WL-SMCW_0603_150060xx75020 [mm] "SMD Mono-color Chip LED, body 1.6x0.8mm"
  rect 0.8x0.8 smd: 1(-0.8,0) 2(0.8,0)
  silkscreen extent -1.62,-0.08 -1.48,0.07, body extent -0.8,-0.4 0.8,0.4, height 0.25

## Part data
C1 C2: library part CMP-06035-061124-1, "GQM1875C2E4R0BB12D / Ceramic Capacitor 4pF ±0.1pF 250VDC C0G 0603 Paper T/R", Case Code (Imperial)=0603, Case Code (Metric)=1608, Dielectric=C0G, Max Operating Temperature=125°C, Min Operating Temperature=-55°C, Package Quantity=4000, Voltage Rating=250V
C3: library part CMP-2007-03343-2, "Ceramic Capacitor for Automotive 4.7uF ±10% 16VDC X7R 0805 Embossed T/R", Case Code (Imperial)=0805, Case Code (Metric)=2012, Dielectric=X7R, Max Operating Temperature=125°C, Min Operating Temperature=-55°C, Package Quantity=1, Ratings=AEC-Q200, Tolerance=10%, Voltage=16V
C4 C5 C6 C7 C25: library part CMP-13271-002683-1, "Cap Ceramic 100nF 16V X7R ±10% Pad SMD 0603 +125°C T/R", Case Code (Imperial)=0603, Case Code (Metric)=1608, Max Operating Temperature=125°C, Min Operating Temperature=-55°C, Ratings=AEC-Q200, Tolerance=10%, Voltage Rating=16V
C8 C9 C22: library part CMP-13271-002683-1, "Cap Ceramic 100nF 16V X7R ±10% Pad SMD 0603 +125°C T/R / CL10B104KO8WPNC", Case Code (Imperial)=0603, Case Code (Metric)=1608, Max Operating Temperature=125°C, Min Operating Temperature=-55°C, Ratings=AEC-Q200, Tolerance=10%, Voltage Rating=16V
C10: library part GRM31C5C1E104JA01L, "Capacitor", Manufacturer_Name="Murata Electronics", Mouser Part Number=81-GRM31C5C1E104JA01
C11 C12 C13 C14 C15: library part CMP-2007-00135-2, "Chip Multilayer Ceramic Capacitors for General Purpose, 0805, 10000pF, C0G, 30ppm/°C, 5%, 50V", Capacitance=10nF, Case Code (Imperial)=0805, Case Code (Metric)=2012, Dielectric=C0G, Dielectric Material=Ceramic, Insulation Resistance=10GR, Max Operating Temperature=125°C, Min Operating Temperature=-55°C, Package Quantity=1, Temperature Coefficient=30ppm/°C, Tolerance=5%, Voltage=50V
C16: library part CMP-13271-000784-1, "Cap Ceramic 1uF 16V X7R ±10% Pad SMD 0603 +125°C T/R / CL10B105KO8NNNL", Case/Package=0603, Dielectric=X7R, Max Operating Temperature=125°C, Min Operating Temperature=-55°C, Package Quantity=15000, Tolerance=10%, Voltage Rating=16V
C17: library part CMP-001-00018-6, "Chip Capacitor, 100 nF, +/- 10%, 50 V, 0805 (2012 Metric)", Capacitor Type=Ceramic, Case/Package=0805, Max Operating Temperature=125°C, Min Operating Temperature=-55°C, Tolerance=10%, Voltage Rating=50V
C18 C20: library part CMP-001-00098-1, "Ceramic Capacitor, Multilayer, Ceramic, 50V, 10% +Tol, 10% -Tol, X7R, 15% TC, 0.47uF, Surface Mount, 0805", Capacitor Type=Ceramic, Case/Package=0805, Max Operating Temperature=125°C, Min Operating Temperature=-55°C, Package Shape=Rectangular, Package Style=SMTMeter, Rated DC Voltage (URdc)=50V, Temperature Characteristics Code=X7R, Tolerance  (fill in as +-)=10%
C19: library part CMP-001-00099-1, "Ceramic Capacitor, Multilayer, Ceramic, 50V, 10% +Tol, 10% -Tol, X7R, 15% TC, 10uF, Surface Mount, 1206", Capacitor Type=Ceramic, Case/Package=1206, Max Operating Temperature=125°C, Min Operating Temperature=-55°C, Package Shape=Rectangular, Package Style=SMTMeter, Rated DC Voltage (URdc)=50V, Temperature Characteristics Code=X7R, Tolerance  (fill in as +-)=10%
C21: library part CMP-001-00103-1, "Ceramic Capacitor, Multilayer, Ceramic, 10V, 10% +Tol, 10% -Tol, X5R, 15% TC, 47uF, Surface Mount, 1206", Capacitor Type=Ceramic, Case/Package=1206, Max Operating Temperature=85°C, Min Operating Temperature=-55°C, Package Shape=Rectangular, Package Style=SMTMeter, Rated DC Voltage (URdc)=10V, Temperature Characteristics Code=X5R, Tolerance  (fill in as +-)=10%
C23 C24: library part CMP-13271-003287-1, "Cap Ceramic 10uF 16V X6S ±20% Pad SMD 0603 +105°C T/R / CL10X106MO8NRNC", Case Code (Imperial)=0603, Case Code (Metric)=1608, Max Operating Temperature=105°C, Min Operating Temperature=-55°C, Tolerance=20%, Voltage Rating=16V
D1: library part CMP-03913-90235563-2, "150060GS55040 WL-SMCD SMT Mono-color Chip LED Diffused", Forward Current=60mA, Forward Voltage=3.2V, Max Operating Temperature=85°C, Max Reverse Voltage (DC)=5V, Min Operating Temperature=-40°C
D2: library part CMP-03913-104891429-2, "WL-SMCW SMT Mono-Color Chip LED Waterclear super f", Forward Current=60mA, Forward Voltage=2V, Max Operating Temperature=85°C, Max Reverse Voltage (DC)=5V, Min Operating Temperature=-40°C
D3: library part CMP-2000-07095-2, "TVS DIODE 33V 53.3V DO214AA", Breakdown Voltage=36.7V, Clamping Voltage=53.3V, Manufacturer="Littelfuse Inc", Max Junction Temp=+150°C, Package=SMBJ, Peak Pulse Current=11.3A, Peak Pulse Power=600W, Reverse Standoff Voltage=33V, Temperature="-65°C to +150°C", Temperature Range Low=-65°C
D4: library part CMP-1426-00001-4, "LED Low-Power Uni-Color Red 630nm 2V 2-Pin Chip 0603(1608Metric) T/R", Case Code (Imperial)=0603, Case Code (Metric)=1608, Color=Red, Forward Current=100mA, Forward Voltage=2V, Max Junction Temperature (Tj)=95°C, Max Operating Temperature=85°C, Max Reverse Voltage (DC)=5V, Min Operating Temperature=-40°C, Power Dissipation=72mW, Test Current=20mA
IC1: "Integrated Circuit", Manufacturer_Name=STMicroelectronics, Mouser Part Number=511-STM32G0B1CBT6
IC2: "Integrated Circuit", Manufacturer_Name="Texas Instruments", Mouser Part Number=595-ADS1234IPWR
J1: "Connector", Manufacturer_Name=SAMTEC, Mouser Part Number=200-FTSH10701LDVKTR
J2 J3 J4 J5 J6 J7 J8 J9: "Connector", Arrow Part Number=S2B-PH-SM4-TB(LF)(SN), Manufacturer_Name="JST (JAPAN SOLDERLESS TERMINALS)", Mouser Part Number=N/A
J10 J11: library part CMP-002-00113-1, "Connector Header, PH Series, 3 Position, Side Entry, 2.00mm, Solder, Surface Mount, Natural.", Max Current Rating=2A, Max Operating Temperature=85°C, Min Operating Temperature=-25°C, Voltage Rating=100V
J12: library part CMP-00257-07672643-1, "43650-0205 Conn Wire to Board HDR 2 POS 3mm Solder RA Side Entry Thru-Hole Micro-Fit 3.0™ Tray", Current Rating=5A, Manufacturer Lifecycle Status=ACTIVE, Voltage Rating=600V
L1: library part CMP-006-00028-1, "General Purpose Inductor"
R1 R23 R24 R29 R30: library part CMP-03412-005349-1, "RES SMD 10K OHM 1% 1/10W 0603 / RT0603FRE0710KL", Manufacturer=Yageo, Manufacturer Part Number=RT0603FRE0710KL, Package=RT0603, Power Rating=0.1W, Resistance=10KΩ, Temperature="-55°C to +155°C", Temperature Coefficient="50 ppm/°C", Temperature Range High=+155°C, Temperature Range Low=-55°C, Tolerance=0.01, Voltage Rating=75V
R2 R3 R28: library part CMP-03412-038529-1, "AF0603JR-07220RL Anti-Sulfurated Chip Resistors Automotive Grade 220Ω 5% 100ppm/°C 0603", Case/Package=0603, Max Operating Temperature=155°C, Max Power Dissipation=100mW, Min Operating Temperature=-55°C, Resistance=220R, Resistor Type="Thick Film", Temperature Coefficient=100ppm/°C, Tolerance=5%
R4: library part CMP-03412-030646-1, "RT0603 100Ω 0.1W 50 ppm/°C 1.00% RT0603FRE07100RL", Manufacturer=Yageo, Manufacturer Part Number=RT0603FRE10100RL, Package=RT0603, Power Rating=0.1W, Resistance=100Ω, Temperature="-55°C to +155°C", Temperature Coefficient="50 ppm/°C", Temperature Range High=+155°C, Temperature Range Low=-55°C, Tolerance=0.01, Voltage Rating=75V
R5 R6 R7 R8 R9 R10 R21 R22: library part CMP-2001-00588-1, Manufacturer=Panasonic, Part Number=ERA6AEB121V
R11 R12 R13 R14 R15 R16 R17 R18 R19 R20: library part CMP-2000-00870-2, "RES SMD 100 OHM 0.1% 1/10W 0603", Case Code (Imperial)=0603, Case Code (Metric)=1608, Max Operating Temperature=155°C, Max Power Dissipation=100mW, Min Operating Temperature=-55°C, Package Quantity=5000, Resistance=100R, Resistance Tolerance=0.1%, Resistor Type="Thin Film", Temperature Coefficient=25ppm/°C, Voltage Rating=75V
R25: library part CMP-03412-039700-1, "Anti-Sulfurated Chip Resistors Automotive Grade 120Ω 1% 100ppm/°C 0603 AF0603FR-07120RL", Case/Package=0603, Max Operating Temperature=155°C, Max Power Dissipation=100mW, Min Operating Temperature=-55°C, Resistance=120R, Resistor Type="Thick Film", Temperature Coefficient=100ppm/°C, Tolerance=1%
R26: library part CMP-009-00192-1, "Fixed Resistor, Metal Glaze/thick Film, 0.25W, 100000ohm, 200V, 1% +/-Tol, 100ppm/Cel, Surface Mount, 1206", Resistor Type="FIXED RESISTOR"
R27: library part CMP-009-00195-1, "Fixed Resistor, Thin Film, 0.125W, 18700ohm, 100V, 0.1% +/-Tol, 25ppm/Cel, Surface Mount, 0805", Case/Package=0805, Max Operating Temperature=155°C, Min Operating Temperature=-55°C, Package Height=0.5mm, Package Length=2mm, Package Width=1.25mm, Power=125mW, Rated Temperature=85°C, Resistor Type="FIXED RESISTOR", Temperature Coefficient (ppm/Cel)=25, Tolerance=0.1%, Working Voltage=100V
U1: "Integrated Circuit", Manufacturer_Name="Texas Instruments", Mouser Part Number=595-TCAN3414DR
U2: library part CMP-019-00059-1, "SIMPLE SWITCHER® 4.5-V to 65-V, 1-A synchronous buck converter with 25-µA IQ 6-SOT-23 -40 to 150", Case/Package=SOT-23, Frequency=400Hz, Max Supply Voltage=65V, Min Supply Voltage=4.5V, Output Current=1A
U3: library part CMP-12153-000011-1, "IC REG LINEAR 3.3V 2A 6DFN", Case/Package=DFN, Dropout Voltage=130mV, Max Input Voltage=6V, Max Operating Temperature=125°C, Min Input Voltage=1.25V, Min Operating Temperature=-40°C, Operating Supply Current=1mA, Output Current=2A, Output Voltage=3.3V, Package Quantity=3000
U4: library part CMP-00370-103943066-1, "TMP461AIRUNR-S Temperature Sensor Digital, Local/Remote -40°C ~ 125°C 11 b 10-WQFN (2x2)", Manufacturer Lifecycle Status=ACTIVE
Y1: library part CMP-27762-007472-1, "Crystal 50MHz ±10ppm 4pF SMD-4 2.5mm x 2mm", Case/Package=SMD/SMT, ESR (Equivalent Series Resistance)=70R, Frequency=50MHz, Frequency Stability=10ppm, Load Capacitance=4pF, Max Operating Temperature=70°C, Min Operating Temperature=-20°C

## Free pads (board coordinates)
  round 5.08 hole 3.2: 2(5,5) 2(5,60) 2(60,5) 2(60,60)

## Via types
v1: diameter 0.61, hole 0.305, Top Layer 1 to Bottom Layer 1, tented both sides, 250 vias

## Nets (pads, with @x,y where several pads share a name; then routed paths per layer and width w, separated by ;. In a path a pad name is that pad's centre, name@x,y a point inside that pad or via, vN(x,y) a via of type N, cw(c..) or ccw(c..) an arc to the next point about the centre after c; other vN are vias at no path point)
3V3: C3.1 C4.1 C5.1 C6.1 C8.1 C9.1 C16.1 C24.1 C25.1 D4.2 IC1.4 IC1.5 IC1.6 IC2.1 IC2.22 J1.3 J2.1 J4.1 J6.1 J8.1 R5.2 R7.2 R9.2 R20.1 R21.2 R29.1 R30.2 U1.3 U3.1 U3.2 U4.1 | length 38.7
  Top Layer 1 w0.25: J4.1 17,52.234 R7.2 ; J8.1@28,54.996 J8.1@28.004,54.996
  Top Layer 1 w0.254: U3.2 U3.2@11.1,15.562 ; v1(17.792,39.19) 19.204,39.19 R20.1 ; v1(34.977,33.5) 34.977,35.177 35.075,35.275 IC2.1 ; J6.1 39,55.373 J6.1@39.373,55 ; J2.1 50,55.373 J2.1@50.373,55
  Top Layer 1 w0.45: C8.1@26.427,38.227 26.427,38.254 26.581,38.408 26.592,38.408 27.359,39.175 v1(27.875,39.175) IC2.22
  Top Layer 1 w0.5: v1(35.817,53.485) 37.844,53.485 R9.2@39.328,52
  Top Layer 1 w0.508: J8.1 28,52.303 R21.2
  Top Layer 1 w0.635: v1(38.933,24.365) 40.242,24.365 C16.1 40.258,24.365 U1.3
  Top Layer 1 w0.75: v1(8.3,35.04) J1.3 ; v1(29.65,18.62) D4.2 ; R9.2@39.328,52 R9.2
  Top Layer 1 w1: R7.2@17.234,52 v1(19,52) ; R21.2 v1(30.25,52.004) ; J6.1@39.373,55 v1(40.5,55) ; v1(46,52) R5.2 ; J2.1@50.373,55 v1(51.5,55)
  other v1: 14.307,16.5 40.559,17.25 12.658,18 14.307,18 18.183,26.344 48.276,35.933
5V0: C20.1 C21.1 C22.1 C23.1 L1.2 R26.1 U3.5 U3.6 | length 22.8
  Top Layer 1 w0.152: C20.1 C20.1@11.876,4.626 ; C22.1 C22.1@12.05,11.299 ; U3.6@11.982,12.879 U3.6
  Top Layer 1 w0.254: C20.1@12.05,4.5 12.05,1.899 12.199,1.75 30.573,1.75 30.722,1.899 30.722,1.948 30.911,2.137 31.138,2.137 R26.1
AINN1: C11.2 IC2.12 R12.2 | length 15.7
  Top Layer 1 w0.4: IC2.12@36,42.425 46.421,42.425 48.177,44.181 48.177,45.269 47.8,45.646 R12.2
AINN2: C14.1 IC2.17 R17.2 | length 15.6
  Top Layer 1 w0.4: R17.2 17.303,45.103 17,44.8 17.431,44.369 17.431,44.319 18.25,43.5 24.218,43.5 25.293,42.425 IC2.17
AINN3: C12.2 IC2.14 R14.2 | length 4.5
  Top Layer 1 w0.4: IC2.14 36.572,43.725 37.397,44.55 37.397,44.6 37.397,44.65 36.903,45.144 R14.2
AINN4: C13.1 IC2.15 R15.2 | length 4.6
  Top Layer 1 w0.45: C13.1 28.937,44.35 IC2.15 ; C13.1@27.601,44.452 27.774,44.625 27.774,46.123 28.202,46.551 R15.2
AINP1: C11.1 IC2.11 R11.2 | length 18.1
  Top Layer 1 w0.4: IC2.11 47.358,41.775 49.764,44.181 49.764,45.147 50.123,45.506 50.123,46.697 R11.2
AINP2: C14.2 IC2.18 R18.2 | length 17.9
  Top Layer 1 w0.4: R18.2 15.05,45.25 15.5,44.8 C14.2@15.5,44.621 ; C14.2@15.423,44.8 15.777,44.446 15.777,43.895 16.922,42.75 23.756,42.75 24.731,41.775 IC2.18
AINP3: C12.1 IC2.13 R13.2 | length 6.6
  Top Layer 1 w0.4: IC2.13 38.075,43.075 38.897,43.897 C12.1@38.897,44.6 ; C12.1@38.897,44.65 39.403,45.156 R13.2
AINP4: C13.2 IC2.16 R16.2 | length 6.7
  Top Layer 1 w0.4: R16.2 25.871,44.426 26.301,43.996 26.301,43.489 26.715,43.075 IC2.16
CANH: J10.2 J11.2 R25.2 U1.7 | length 27.1
  Top Layer 1 w0.254: U1.7 47.977,25.65 53.148,25.65 R25.2 ; R25.2@53.18,25.671 53.388,25.879 53.48,25.879 54.521,26.92 54.521,30.994 55.127,31.601 55.127,31.627 J10.2@55.5,32 ; J10.2 55.504,32 55.131,32.373 55.131,32.662 54.341,33.452 54.341,42.037 54.917,42.613 55.113,42.613 55.5,43 J11.2
CANL: J10.3 J11.3 R25.1 U1.6 | length 27.4
  Top Layer 1 w0.254: U1.6@47.962,24.344 47.983,24.323 R25.1@53.154,24.323 ; R25.1 53.251,24.323 55.332,26.404 55.332,29.627 55.705,30 J10.3 57.123,30.373 58.434,30.373 59,30.939 59,39.979 58.732,40.247 58.373,40.606 58.373,40.627 58,41 J11.3
CB: C17.2 U2.1 | length 2.3
  Top Layer 1 w0.25: C17.2 32.325,9.2 U2.1
FB: R26.2 R27.1 U2.3 | length 7.1
  Top Layer 1 w0.25: R26.2@31.751,5.25 33.25,5.25 ; 33.25,7.251 33.25,5.25 ; R27.1 33.25,5.25
  Top Layer 1 w0.254: 33.25,7.251 33.299,7.3 U2.3
  Top Layer 1 w0.4: R26.2 R26.2@31.751,5.25
GND: C1.2 C2.2 C3.2 C4.2 C5.2 C6.2 C7.2 C8.2 C9.2 C16.2 C18.2 C19.2 C20.2 C21.2 C22.2 C23.2 C24.2 C25.2 D3.2 IC1.7 IC2.2 IC2.3 IC2.5 IC2.6 IC2.21 IC2.25 J1.5 J1.7 J2.MP1 J2.MP2 J3.2 J3.MP1 J3.MP2 J4.MP1 J4.MP2 J5.2 J5.MP1 J5.MP2 J6.MP1 J6.MP2 J7.2 J7.MP1 J7.MP2 J8.MP1 J8.MP2 J9.2 J9.MP1 J9.MP2 J10.1 J10.4 J10.5 J11.1 J11.4 J11.5 J12.2 J12.3 J12.4 R1.2 R2.1 R3.1 R4.1 R6.1 R8.1 R10.1 R19.1 R22.1 R23.2 R24.2 R27.2 R28.1 U1.2 U2.2 U3.3 U3.7 U4.5 U4.6 U4.10 Y1.2 Y1.4 | length 6
  Top Layer 1 w0.152: Y1.2 24.848,23.286 24.848,23.536 25.261,23.949 25.699,24.388 Y1.4
  Top Layer 1 w0.254: U3.3 U3.3@10.15,15.562 ; U1.2@42.534,25.631 U1.2 ; U4.6 U4.6@45.5,33.121
  Top Layer 1 w0.635: C16.2@40.161,25.689 40.188,25.689 C16.2 40.254,25.631 U1.2@42.534,25.631
  Bottom Layer 1 w0.254: J7.2 J7.2@39,57.5
  other v1: 8.5,3.5 29.5,3.5 38.5,3.5 41.5,3.5 44.5,3.5 47.5,3.5 50.5,3.5 53.5,3.5 56.5,3.5 28,6.5 46,6.5 49,6.5 52,6.5 55,6.5 64,6.5 5.5,9.5 8.5,9.5 29.5,9.5 35.5,9.5 44.5,9.5 47.5,9.5 50.5,9.5 53.5,9.5 62.5,9.5 7,12.5 28,12.5 31,12.5 34,12.5 37,12.5 64,12.5 5.5,15.5 8.5,15.5 17.5,15.5 20.5,15.5 23.5,15.5 26.5,15.5 29.5,15.5 35.5,15.5 38.5,15.5 41.5,15.5 44.5,15.5 59.5,15.5 62.5,15.5 7,18.5 10,18.5 16,18.5 19,18.5 22,18.5 28,18.5 37,18.5 43,18.5 46,18.5 64,18.5 5.5,21.5 8.5,21.5 11.5,21.5 14.5,21.5 20.5,21.5 22.533,21.493 38.5,21.5 44.5,21.5 47.5,21.5 50.5,21.5 53.5,21.5 56.5,21.5 59.5,21.5 62.5,21.5 7,24.5 10,24.5 13,24.5 16,24.5 34,24.5 46,24.5 55,24.5 58,24.5 61,24.5 64,24.5 5.5,27.5 11.5,27.5 32.5,27.5 53.5,27.5 56.5,27.5 59.5,27.5 13,30.5 19,30.5 22,30.5 25,30.5 43,30.5 49,30.5 52,30.5 61,30.5 64,30.5 5.5,33.5 8.5,33.5 32.5,33.5 33.723,33.5 38.5,33.5 41.5,33.5 44.5,33.5 50.5,33.5 53.5,33.5 62.5,33.5 7,36.5 13,36.5 19,36.5 22,36.5 25,36.5 31,36.5 34,36.5 40,36.5 43,36.5 46,36.5 52,36.5 58,36.5 5.5,39.5 8.5,39.5 11.5,39.5 14.5,39.5 26.5,39.5 32.5,39.5 44.5,39.5 47.5,39.5 50.5,39.5 53.5,39.5 56.5,39.5 7,42.5 10,42.5 13,42.5 16,42.5 31,42.5 34,42.5 52,42.5 61,42.5 64,42.5 5.5,45.5 8.5,45.5 11.5,45.5 20.5,45.5 23.5,45.5 29.5,45.5 32.5,45.5 35.5,45.5 41.5,45.5 44.5,45.5 53.5,45.5 59.5,45.5 62.5,45.5 7,48.5 10,48.5 19,48.5 22,48.5 31,48.5 34,48.5 43,48.5 46,48.5 49,48.5 52,48.5 55,48.5 58,48.5 5.5,51.5 8.5,51.5 11.5,51.5 20.5,51.5 32.5,51.5 35.5,51.5 41.5,51.5 44.5,51.5 53.5,51.5 56.5,51.5 59.5,51.5 62.5,51.5 7,54.5 10,54.5 19,54.5 22,54.5 31,54.5 34,54.5 43,54.5 55,54.5 58,54.5 61,54.5 64,54.5 8.5,57.5 11.5,57.5 20.5,57.5 23.5,57.5 29.5,57.5 32.5,57.5 35.5,57.5 41.5,57.5 44.5,57.5 53.5,57.5 56.5,57.5 62.5,57.5 10,60.5 16,60.5 22,60.5 25,60.5 28,60.5 37,60.5 40,60.5 43,60.5 49,60.5 55,60.5 64,60.5 5.5,63.5 8.5,63.5 14.5,63.5 17.5,63.5 26.5,63.5 32.5,63.5 38.5,63.5 47.5,63.5 50.5,63.5 56.5,63.5 59.5,63.5
LEDG: D1.2 IC1.19 | length 2.2
  Top Layer 1 w0.152: D1.2@32.75,18.895 IC1.19
  Top Layer 1 w0.254: D1.2 32.5,18.645 D1.2@32.75,18.895
LEDY: D2.2 IC1.20 | length 2.3
  Top Layer 1 w0.152: IC1.20 33.25,19.12 D2.2
N1: R5.1 R6.2 R12.1 | length 4.3
  Top Layer 1 w0.254: R12.1 R5.1 R6.2
N2: R7.1 R8.2 R17.1 | length 4.8
  Top Layer 1 w0.25: R8.2 15.213,50.55 16.784,50.55 17.303,50.031 R17.1
N3: R9.1 R10.2 R14.1 | length 4.6
  Top Layer 1 w0.254: R14.1 36.903,50.003 R10.2 R9.1
N4: R15.1 R21.1 R22.2 | length 4.7
  Top Layer 1 w0.25: R22.2@25.87,50.104 28.059,50.104 R21.1 ; R15.1@27.8,47.976 28.009,48.185 28.009,50.134 R21.1@28.059,50.184
NetC10_1: C10.1 IC2.10 | length 5.5
  Top Layer 1 w0.4: IC2.10 39.81,41.125 40.378,40.557 C10.1@40.753,40.557
NetC10_2: C10.2 IC2.9 | length 6.4
  Top Layer 1 w0.4: IC2.9 37.732,40.475 40.07,38.137 40.07,38.105 40.38,37.795 C10.2
NetD1_1: D1.1 R2.2 | length 1.7
  Top Layer 1 w0.254: R2.2 D1.1
NetD2_1: D2.1 R3.2 | length 2
  Top Layer 1 w0.254: D2.1 34.5,16.27 R3.2
NetD4_1: D4.1 R28.2 | length 2
  Top Layer 1 w0.254: R28.2 30.5,16.27 D4.1
NetIC1_33: IC1.33 U1.4 | length 8.4
  Top Layer 1 w0.152: IC1.33 37.75,26.25 38.05,25.95 38.05,23.75 38.55,23.25 42.383,23.25 U1.4
NetIC1_34: IC1.34 U1.1 | length 5.6
  Top Layer 1 w0.152: IC1.34@37,26.75 42.383,26.75 U1.1
NetJ1_11: J1.11 R4.2 | length 3.3
  Top Layer 1 w0.254: R4.2 7.86,29.96 J1.11
NetR23_1: R23.1 U1.8 | length 2.4
  Top Layer 1 w0.254: U1.8 50.228,26.905 R23.1
NetR24_1: R24.1 U1.5 | length 2.4
  Top Layer 1 w0.254: U1.5 50.228,23.095 R24.1
NetU4_2: U4.2 U4.3 | length 0.5
  Top Layer 1 w0.254: U4.3 U4.2
NRST: C7.1 IC1.10 J1.12 | length 24.3
  Top Layer 1 w0.152: IC1.10 29.437,23.25 v1(30.75,24.563)
  Top Layer 1 w0.254: J1.12 15.227,29.768 16.638,29.768 17,29.406 17,25.479 17.829,24.65 20.325,24.65 C7.1
  Bottom Layer 1 w0.254: v1(20.325,24.674) 21.375,24.674 22.5,25.8 29.513,25.8 v1(30.75,24.563)
P1: J2.2 J3.1 R11.1 | length 16.8
  Top Layer 1 w0.254: v1(46.559,55) 47.627,55 48,55.373 J2.2 48,55 49.232,53.768 51.432,53.768 51.75,53.45 51.75,49.253 50.935,48.438 50.413,48.438 R11.1
  Bottom Layer 1 w0.254: v1(46.559,55) 47.627,55 48,55.373 J3.1
P2: J4.2 J5.1 R18.1 | length 13.9
  Top Layer 1 w0.25: J4.2 15,55.125 14.625,54.75 v1(13.75,54.75) 12.5,53.5 12.5,49.629 14.027,48.101 R18.1
  Bottom Layer 1 w0.254: v1(13.75,54.75) 14.627,54.75 15,55.123 J5.1
P3: J6.2 J7.1 R13.1 | length 15.4
  Top Layer 1 w0.254: v1(35.5,55.111) 36.627,55.111 J6.2@37,55.484 ; J6.2 J6.2@37,55.484 ; R13.1 39.403,48 40.703,49.3 40.703,52.935 39.638,54 38.088,54 37.461,54.627 37.373,54.627 37,55 J6.2@37,55.484
  Bottom Layer 1 w0.254: v1(35.5,55.111) 36.627,55.111 37,55.484 J7.1
P4: J8.2 J9.1 R16.1 | length 14.3
  Top Layer 1 w0.25: J8.2 26,55 25.01,54.01 24.842,54.01 v1(24.774,53.941) 24.049,53.941 23.896,53.788 23.896,48.75 24.671,47.976 R16.1@26.1,47.976
  Bottom Layer 1 w0.254: v1(24.774,53.941) 24.842,54.009 25.009,54.009 26,55 J9.1
REFN: C15.1 IC2.19 R19.2 | length 8.9
  Top Layer 1 w0.4: R19.2 22.929,41.121 C15.1 23.076,41.125 IC2.19
REFP: C15.2 IC2.20 R20.2 | length 9.4
  Top Layer 1 w0.4: R20.2 21.011,39.395 C15.2 23.354,39.749 23.82,39.749 24.546,40.475 IC2.20
SCL: IC1.25 R29.2 U4.9 | length 20.4
  Top Layer 1 w0.254: IC1.25 39,22.25 v1(40,21.25) 39.5,20.75 R29.2 ; U4.9 47,32 v1(47.5,31.5)
  Bottom Layer 1 w0.254: v1(40,21.25) 47.5,28.75 v1(47.5,31.5)
SDA: IC1.26 R30.1 U4.8 | length 20
  Top Layer 1 w0.254: IC1.26 39.5,22.75 v1(40,22.25) 41.5,20.75 R30.1 ; v1(46.5,31) U4.8
  Bottom Layer 1 w0.254: v1(40,22.25) 46.5,28.75 v1(46.5,31)
SG_A0: IC1.42 IC2.8 | length 14.8
  Top Layer 1 w0.254: IC1.42 32.75,30.5 33.592,31.342 35.391,31.342 37.25,33.2 37.25,39 36.425,39.825 IC2.8
SG_A1: IC1.43 IC2.7 | length 13.9
  Top Layer 1 w0.254: IC1.43 32.25,30.695 33.555,32 35.358,32 36.75,33.392 36.75,38.75 36.325,39.175 IC2.7
SG_DRDY/DOUT: IC1.44 IC2.28 | length 6.9
  Top Layer 1 w0.254: IC2.28 29.562,34.188 31.75,32 IC1.44
SG_GAIN0: IC1.48 IC2.23 | length 12.2
  Top Layer 1 w0.254: IC2.23 28.525,38.525 26.906,36.906 26.906,34.039 29.75,31.195 IC1.48
SG_GAIN1: IC1.47 IC2.24 | length 11.3
  Top Layer 1 w0.254: IC2.24 28.625,37.875 27.35,36.6 27.35,34.242 30.25,31.342 IC1.47
SG_PWDN: IC1.46 IC2.26 | length 9.8
  Top Layer 1 w0.254: IC2.26 28.575,36.575 27.9,35.9 27.9,34.338 30.75,31.488 IC1.46
SG_SCLK: IC1.45 IC2.27 | length 8.9
  Top Layer 1 w0.254: IC2.27@29.558,35.929 28.677,35.929 28.41,35.662 28.41,34.59 31.25,31.75 IC1.45
SW: C17.1 L1.1 U2.6 | length 13.5
  Top Layer 1 w0.25: L1.1 25.95,9.65 27.275,10.975 C17.1 35.725,10.975 36.825,9.875 U2.6
SWCLK: IC1.36 J1.6 R1.1 | length 35.2
  Top Layer 1 w0.152: IC1.36 38.05,27.75 R1.1@38.723,28.423
  Top Layer 1 w0.254: J1.6 18.127,33.77 18.254,33.77 18.254,34.265 19.016,34.265 19.016,33.218 19.778,33.218 19.778,34.265 20.54,34.265 20.54,33.218 21.302,33.218 21.302,34.265 22.064,34.265 22.064,33.218 22.826,33.218 22.826,33.77 23.634,33.77 24.33,33.77 v1(26.35,31.75) ; v1(38.294,30.225) 38.294,30.129 38.723,29.699 R1.1
  Bottom Layer 1 w0.254: v1(26.35,31.75) 27.35,30.75 27.9,30.75 37.769,30.75 v1(38.294,30.225)
SWDIO: IC1.35 J1.4 | length 35.5
  Top Layer 1 w0.152: IC1.35 40.75,27.25 v1(42,28.5)
  Top Layer 1 w0.254: J1.4 24.46,35.04 v1(26,33.5)
  Bottom Layer 1 w0.254: v1(26,33.5) 27.994,31.506 39.043,31.506 42,28.549 v1(42,28.5)
VCP_RX: IC1.12 J1.13 | length 24
  Top Layer 1 w0.152: 28.262,20.937 IC1.12
  Top Layer 1 w0.254: J1.13 11.99,28.69 12.233,28.447 12.233,26.316 18.774,19.775 27.1,19.775 28.262,20.937
VCP_TX: IC1.11 J1.14 | length 24.5
  Top Layer 1 w0.254: J1.14 15.035,24.465 18.979,20.521 v1(21.1,20.521) ; v1(22.85,19) 27.281,19 28.852,20.571 28.852,21.336 29.487,21.971 29.487,22.513 29.25,22.75 IC1.11
  Bottom Layer 1 w0.254: v1(21.1,20.521) 21.836,19.784 22.066,19.784 v1(22.85,19)
Vin: C18.1 C19.1 D3.1 J12.1 U2.4 U2.5
XTAL2A: C1.1 IC1.8 Y1.1 | length 6.8
  Top Layer 1 w0.152: C1.1 23.579,24.476 24.413,24.476 Y1.1 24.499,24.738 25.262,25.5 25.981,25.5 26.193,25.5 27.4,24.294 28.218,24.294 IC1.8
XTAL2B: C2.1 IC1.9 Y1.3 | length 5.2
  Top Layer 1 w0.152: C2.1 25.877,21.123 26.28,21.526 26.28,22.182 25.699,22.763 Y1.3 25.699,23.113 26.337,23.75 IC1.9
pads on no net: IC1.1 IC1.2 IC1.3 IC1.13 IC1.14 IC1.15 IC1.16 IC1.17 IC1.18 IC1.21 IC1.22 IC1.23 IC1.24 IC1.27 IC1.28 IC1.29 IC1.30 IC1.31 IC1.32 IC1.37 IC1.38 IC1.39 IC1.40 IC1.41 IC2.4 J1.1 J1.2 J1.8 J1.9 J1.10 U3.4 U4.4 U4.7

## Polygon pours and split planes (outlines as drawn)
GND on Top Layer 1 "GND_L01_P013" (solid, pour order 13): 5,65 ccw(c5,60) 0,60 0,2.54 ccw(c2.54,2.54) 2.54,0 62.46,0 ccw(c62.46,2.54) 65,2.54 65,62.46 ccw(c62.46,62.46) 62.46,65 59,65
Vin on Top Layer 1 "VIN_L01_P012" (solid, pour order 12): 56,18.47 49,18.47 49,13.5 38,13.5 38,8.524 36.5,8.524 36.5,6.25 37.5,6.25 37.5,4.5 41,4.5 41,11 53.5,11 53.5,15.169 56,15.169
3V3 on Top Layer 1 "3V3_L01_P010" (solid, pour order 10): 39.026,18.64 39.026,17.5 40.026,16.5 41.974,16.5 41.974,18.797 39,18.797 39,18.882
3V3 on Top Layer 1 "3V3_L01_P009" (solid, pour order 9): 46.817,34.25 46.817,36.742 49.559,36.75 49.559,34 48.526,34 48.276,34.25 47.817,34.25
3V3 on Top Layer 1 "3V3_L01_P008" (solid, pour order 8): 17.5,27.499 17.5,25.74 26.337,25.8 27.541,25.115 28.997,25.099 28.986,26.385 27.35,26.385 26.085,27.506
5V0 on Top Layer 1 "5V0_L01_P007" (solid, pour order 7): 10.875,12.879 10.875,12.512 11.526,11.861 11.526,8.944 11,8.324 11,3.468 14.612,3.468 14.612,5.987 17.5,5.987 17.5,11.438 15.131,11.438 13.371,12.879
3V3 on Top Layer 1 "3V3 supply" (solid, pour order 0): 10.875,15.382 15.334,15.382 15.405,15.453 15.405,19.012 10.875,19.012
GND on Bottom Layer 1 "GND_L04_P004" (solid, pour order 4): -0.342,5.19 ccw(c5.123,5.19) 5.123,-0.275 59.658,-0.275 ccw(c59.658,4.725) 64.658,4.725 64.658,59.725 ccw(c59.658,59.725) 59.658,64.725 4.658,64.725 ccw(c4.658,59.725) -0.342,59.725
3V3 on 3V3 (split plane): 60.294,64.482 60.586,64.453 60.876,64.406 61.163,64.339 61.444,64.253 61.719,64.15 61.987,64.029 62.246,63.89 62.496,63.735 62.734,63.564 62.962,63.377 63.176,63.176 63.377,62.962 63.564,62.734 63.735,62.496 63.89,62.246 64.029,61.987 64.15,61.719 64.253,61.444 64.339,61.163 64.406,60.876 64.453,60.586 64.482,60.294 64.491,60.018 64.49,60 64.49,5 64.491,4.982 64.482,4.706 64.453,4.414 64.406,4.124 64.339,3.837 64.253,3.556 64.15,3.281 64.029,3.013 63.89,2.754 63.735,2.504 63.564,2.266 63.377,2.038 63.176,1.824 62.962,1.623 62.734,1.436 62.496,1.265 62.246,1.11 61.987,0.971 61.719,0.85 61.444,0.747 61.163,0.661 60.876,0.594 60.586,0.547 60.294,0.518 60.018,0.509 60,0.51 5,0.51 4.982,0.509 4.706,0.518 4.414,0.547 4.124,0.594 3.837,0.661 3.556,0.747 3.281,0.85 3.013,0.971 2.754,1.11 2.504,1.265 2.266,1.436 2.038,1.623 1.824,1.824 1.623,2.038 1.436,2.266 1.265,2.504 1.11,2.754 0.971,3.013 0.85,3.281 0.747,3.556 0.661,3.837 0.594,4.124 0.547,4.414 0.518,4.706 0.509,4.982 0.51,5 0.51,60 0.509,60.018 0.518,60.294 0.547,60.586 0.594,60.876 0.661,61.163 0.747,61.444 0.85,61.719 0.971,61.987 1.11,62.246 1.265,62.496 1.436,62.734 1.623,62.962 1.824,63.176 2.038,63.377 2.266,63.564 2.504,63.735 2.754,63.89 3.013,64.029 3.281,64.15 3.556,64.253 3.837,64.339 4.124,64.406 4.414,64.453 4.706,64.482 4.982,64.491 5,64.49 60,64.49 60.018,64.491
GND on GND (split plane): 60.294,64.482 60.586,64.453 60.876,64.406 61.163,64.339 61.444,64.253 61.719,64.15 61.987,64.029 62.246,63.89 62.496,63.735 62.734,63.564 62.962,63.377 63.176,63.176 63.377,62.962 63.564,62.734 63.735,62.496 63.89,62.246 64.029,61.987 64.15,61.719 64.253,61.444 64.339,61.163 64.406,60.876 64.453,60.586 64.482,60.294 64.491,60.018 64.49,60 64.49,5 64.491,4.982 64.482,4.706 64.453,4.414 64.406,4.124 64.339,3.837 64.253,3.556 64.15,3.281 64.029,3.013 63.89,2.754 63.735,2.504 63.564,2.266 63.377,2.038 63.176,1.824 62.962,1.623 62.734,1.436 62.496,1.265 62.246,1.11 61.987,0.971 61.719,0.85 61.444,0.747 61.163,0.661 60.876,0.594 60.586,0.547 60.294,0.518 60.018,0.509 60,0.51 5,0.51 4.982,0.509 4.706,0.518 4.414,0.547 4.124,0.594 3.837,0.661 3.556,0.747 3.281,0.85 3.013,0.971 2.754,1.11 2.504,1.265 2.266,1.436 2.038,1.623 1.824,1.824 1.623,2.038 1.436,2.266 1.265,2.504 1.11,2.754 0.971,3.013 0.85,3.281 0.747,3.556 0.661,3.837 0.594,4.124 0.547,4.414 0.518,4.706 0.509,4.982 0.51,5 0.51,60 0.509,60.018 0.518,60.294 0.547,60.586 0.594,60.876 0.661,61.163 0.747,61.444 0.85,61.719 0.971,61.987 1.11,62.246 1.265,62.496 1.436,62.734 1.623,62.962 1.824,63.176 2.038,63.377 2.266,63.564 2.504,63.735 2.754,63.89 3.013,64.029 3.281,64.15 3.556,64.253 3.837,64.339 4.124,64.406 4.414,64.453 4.706,64.482 4.982,64.491 5,64.49 60,64.49 60.018,64.491

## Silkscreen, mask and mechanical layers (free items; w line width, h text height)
Top Overlay:
  text "SG4A" at 20.746,62.048 h1.52 r270
  text "SG3A" at 31.746,62.048 h1.52 r270
  text "SG2A" at 42.746,61.798 h1.52 r270
  text "SG1A" at 53.754,61.566 h1.52 r270
  text "CAN" at 58.254,49.254 h1.52
  text "Strain Gauge Node V1.0" at 2.254,47.995 h1.5 r270
  text "PWR" at 58.254,21.254 h1.52
Bottom Overlay:
  text "SG4B" at 20.746,56.484 h1.52 r270
  text "SG3B" at 31.746,56.484 h1.52 r270
  text "SG2B" at 42.746,56.234 h1.52 r270
  text "SG1B" at 53.754,56.254 h1.52 r270
Bottom 3D Body:
  lines w0.254: 0,0 65,0 65,65 0,65 0,0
